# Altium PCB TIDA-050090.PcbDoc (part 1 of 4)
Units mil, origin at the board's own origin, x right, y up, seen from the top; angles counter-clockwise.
Board outline 4150 x 4140 mil, 8 copper layers (Top Layer 1, POWER1, GND1, SIGNAL1, SIGNAL2, GND2, POWER2, Bottom Layer 1), stack 60.703 mil thick; 130 components, 39 nets, 355 pads, 2292 vias.
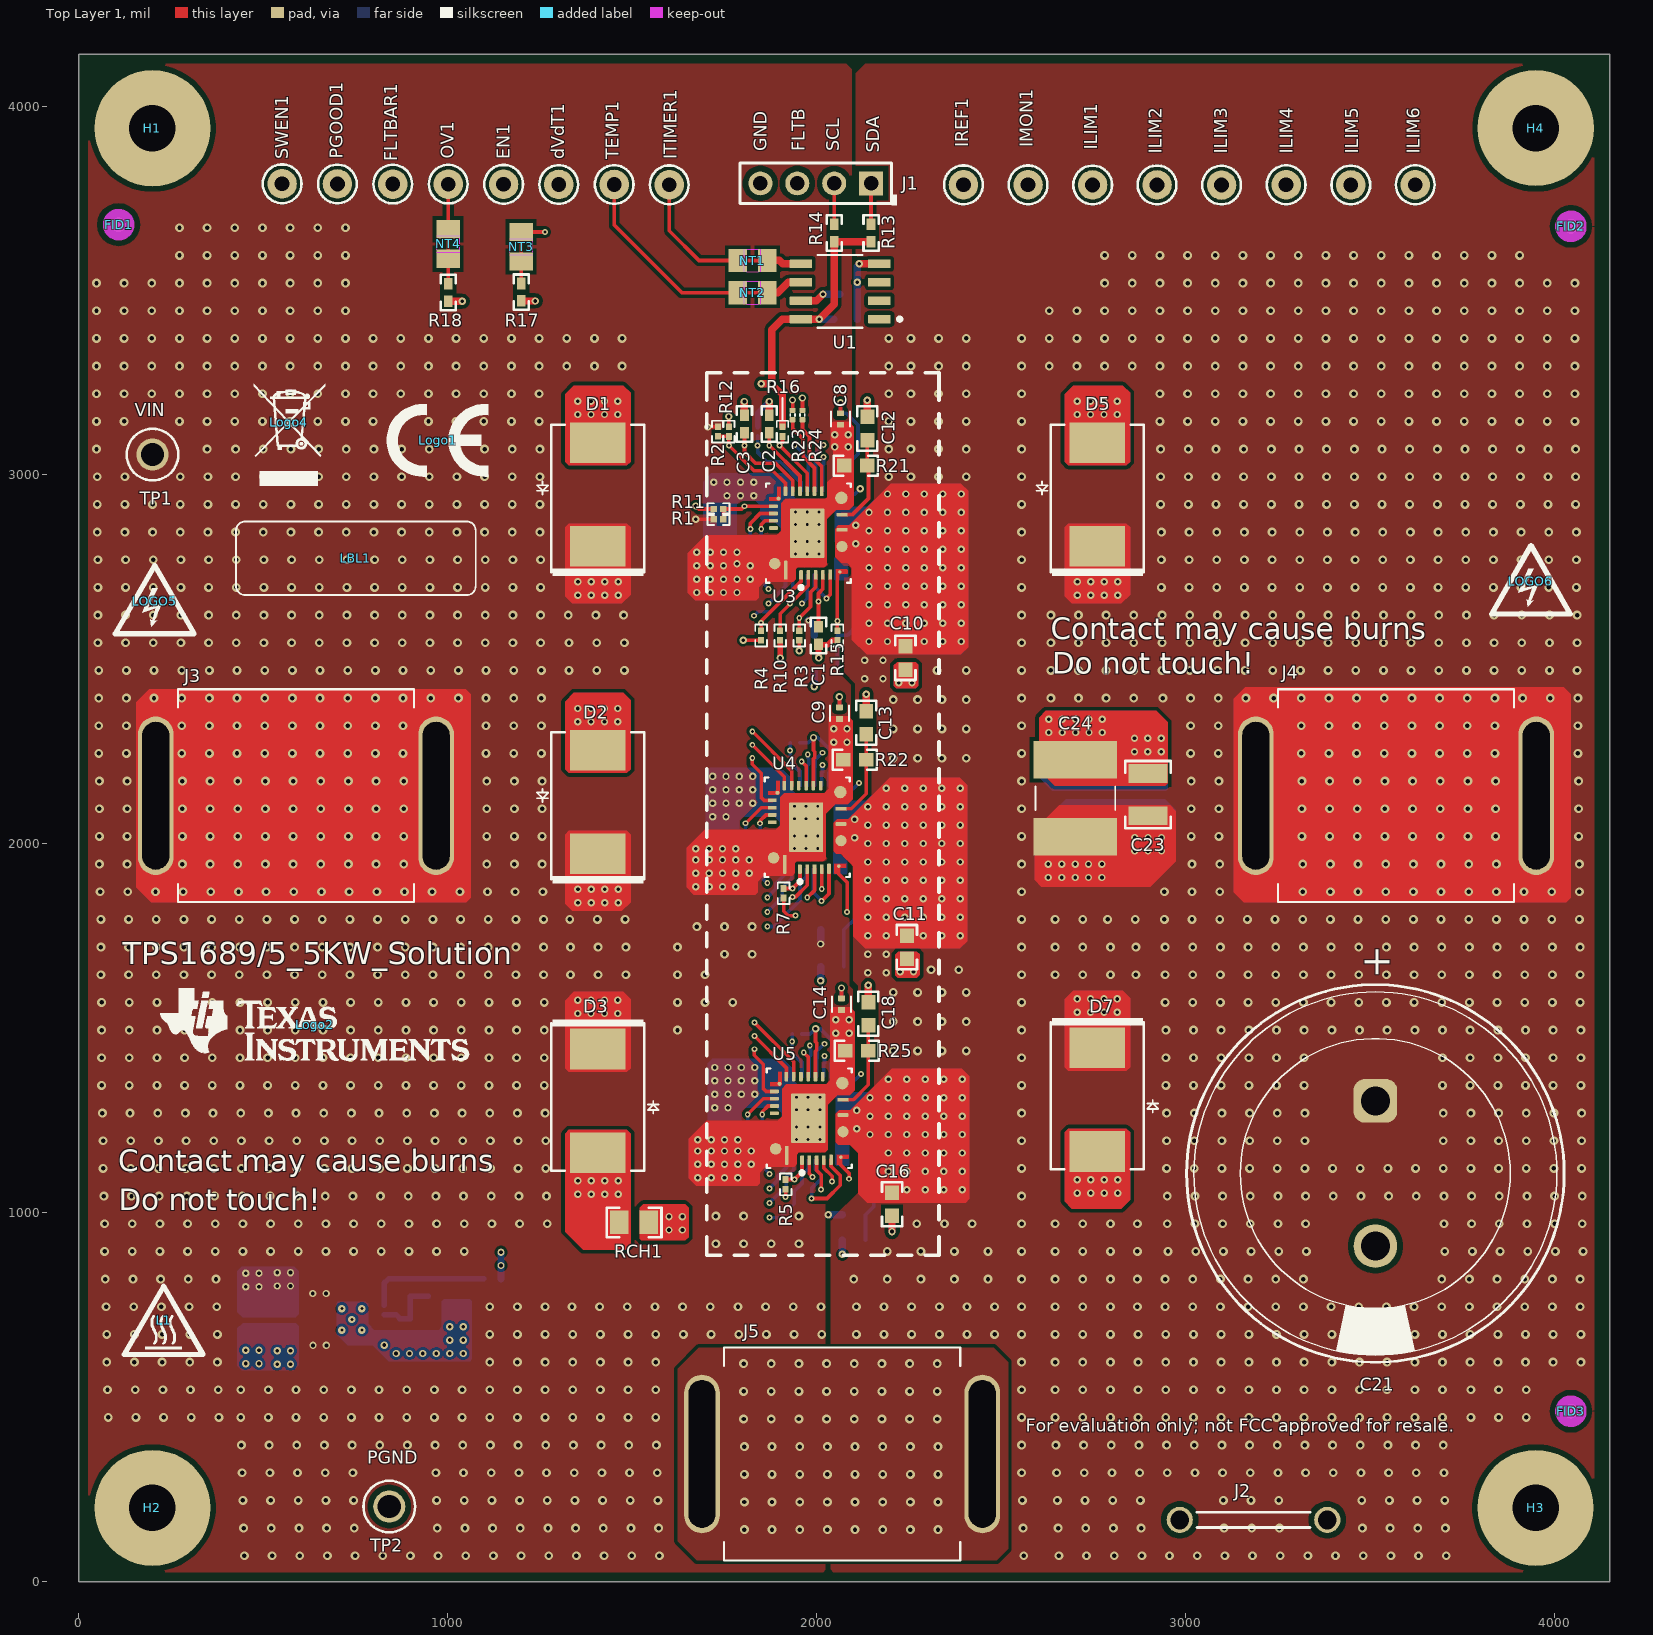
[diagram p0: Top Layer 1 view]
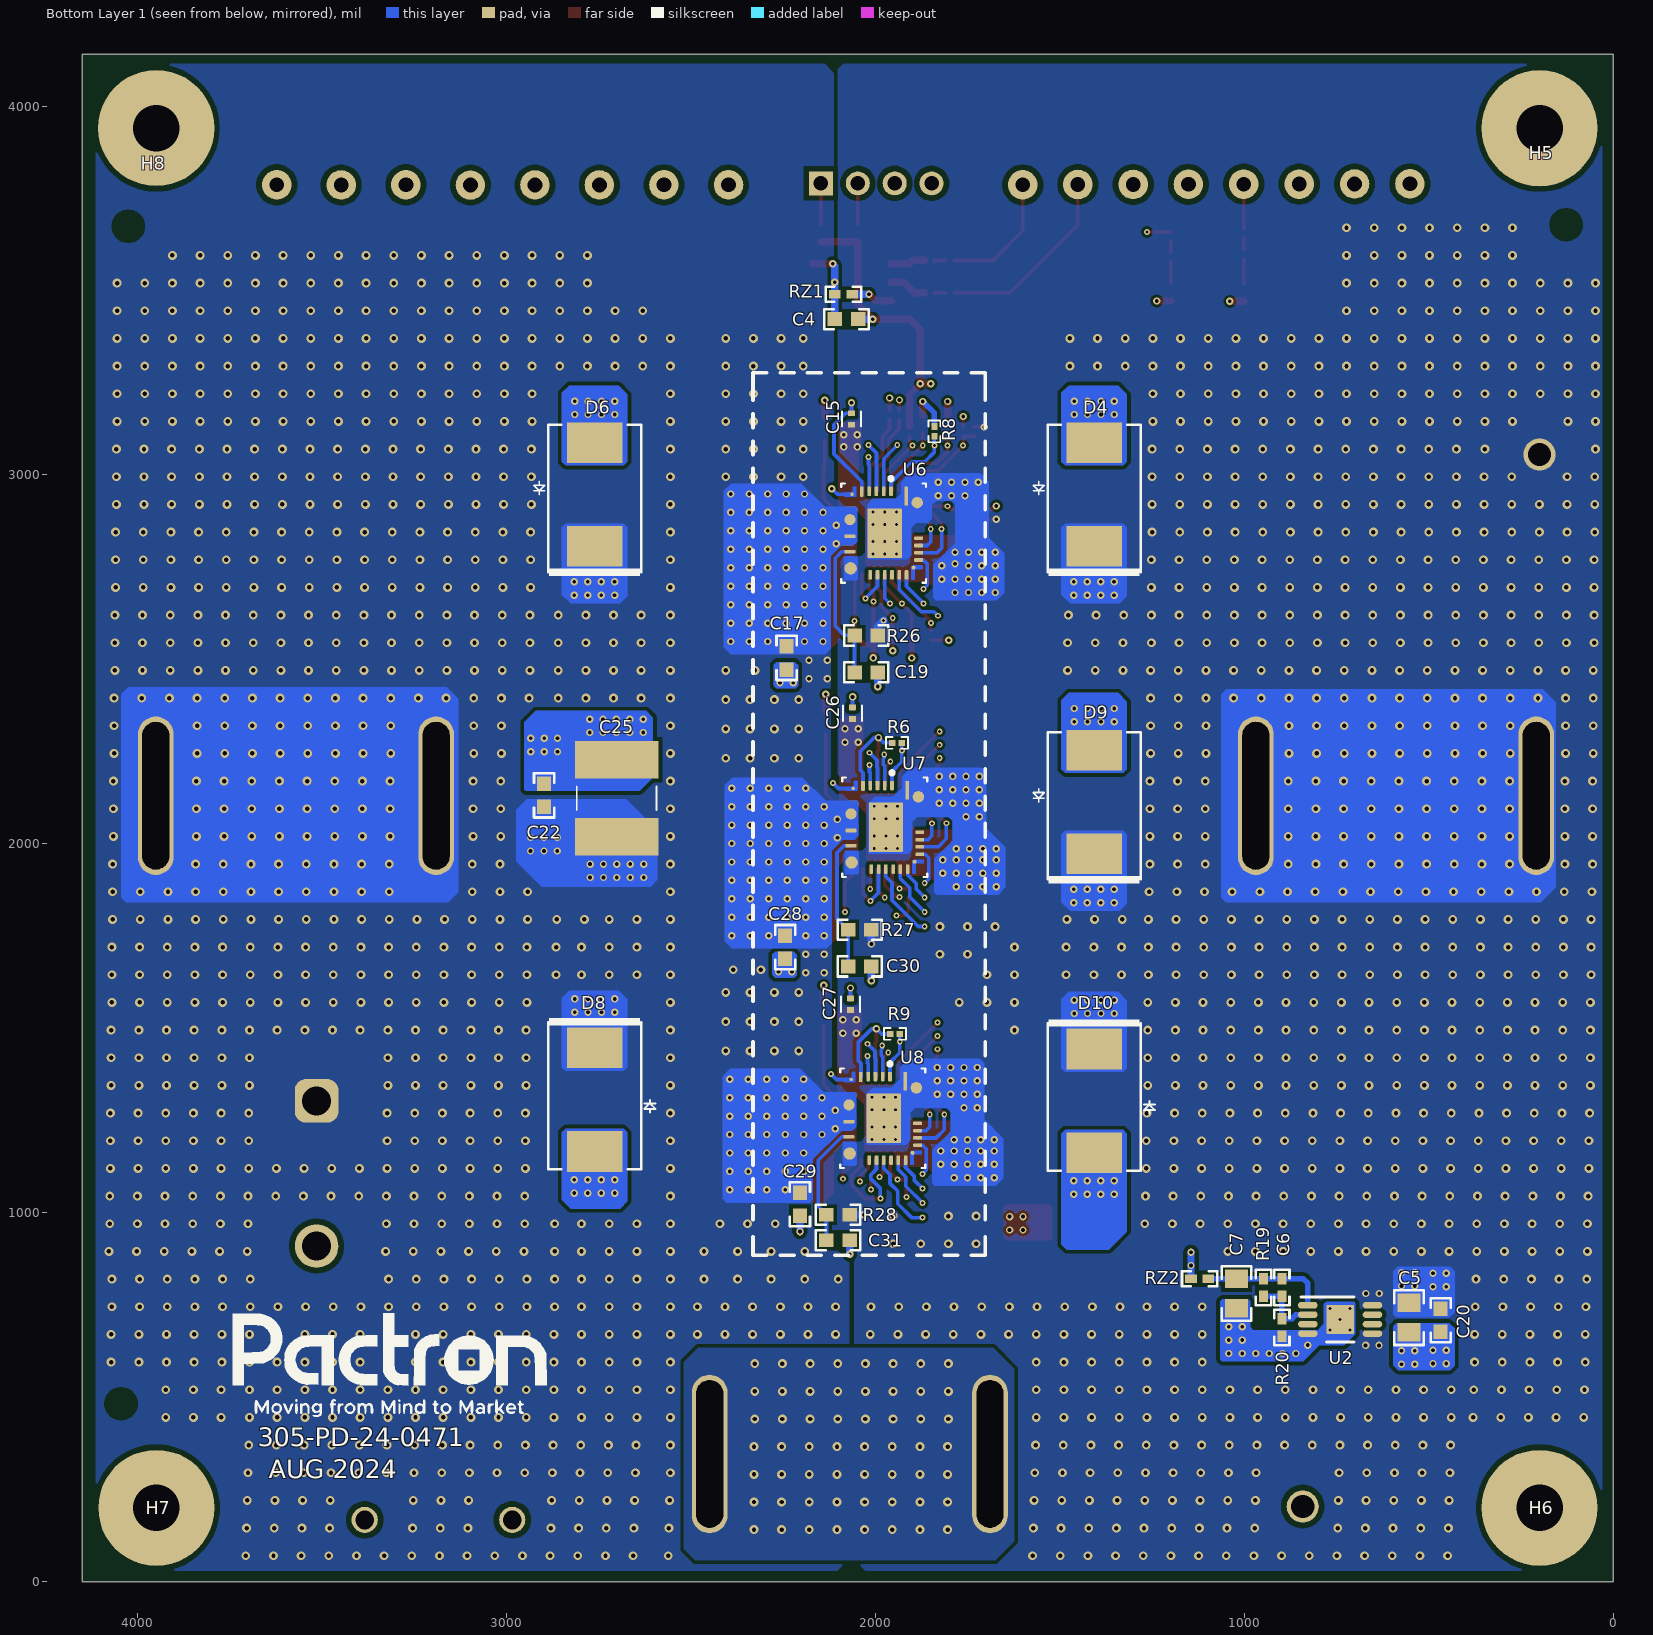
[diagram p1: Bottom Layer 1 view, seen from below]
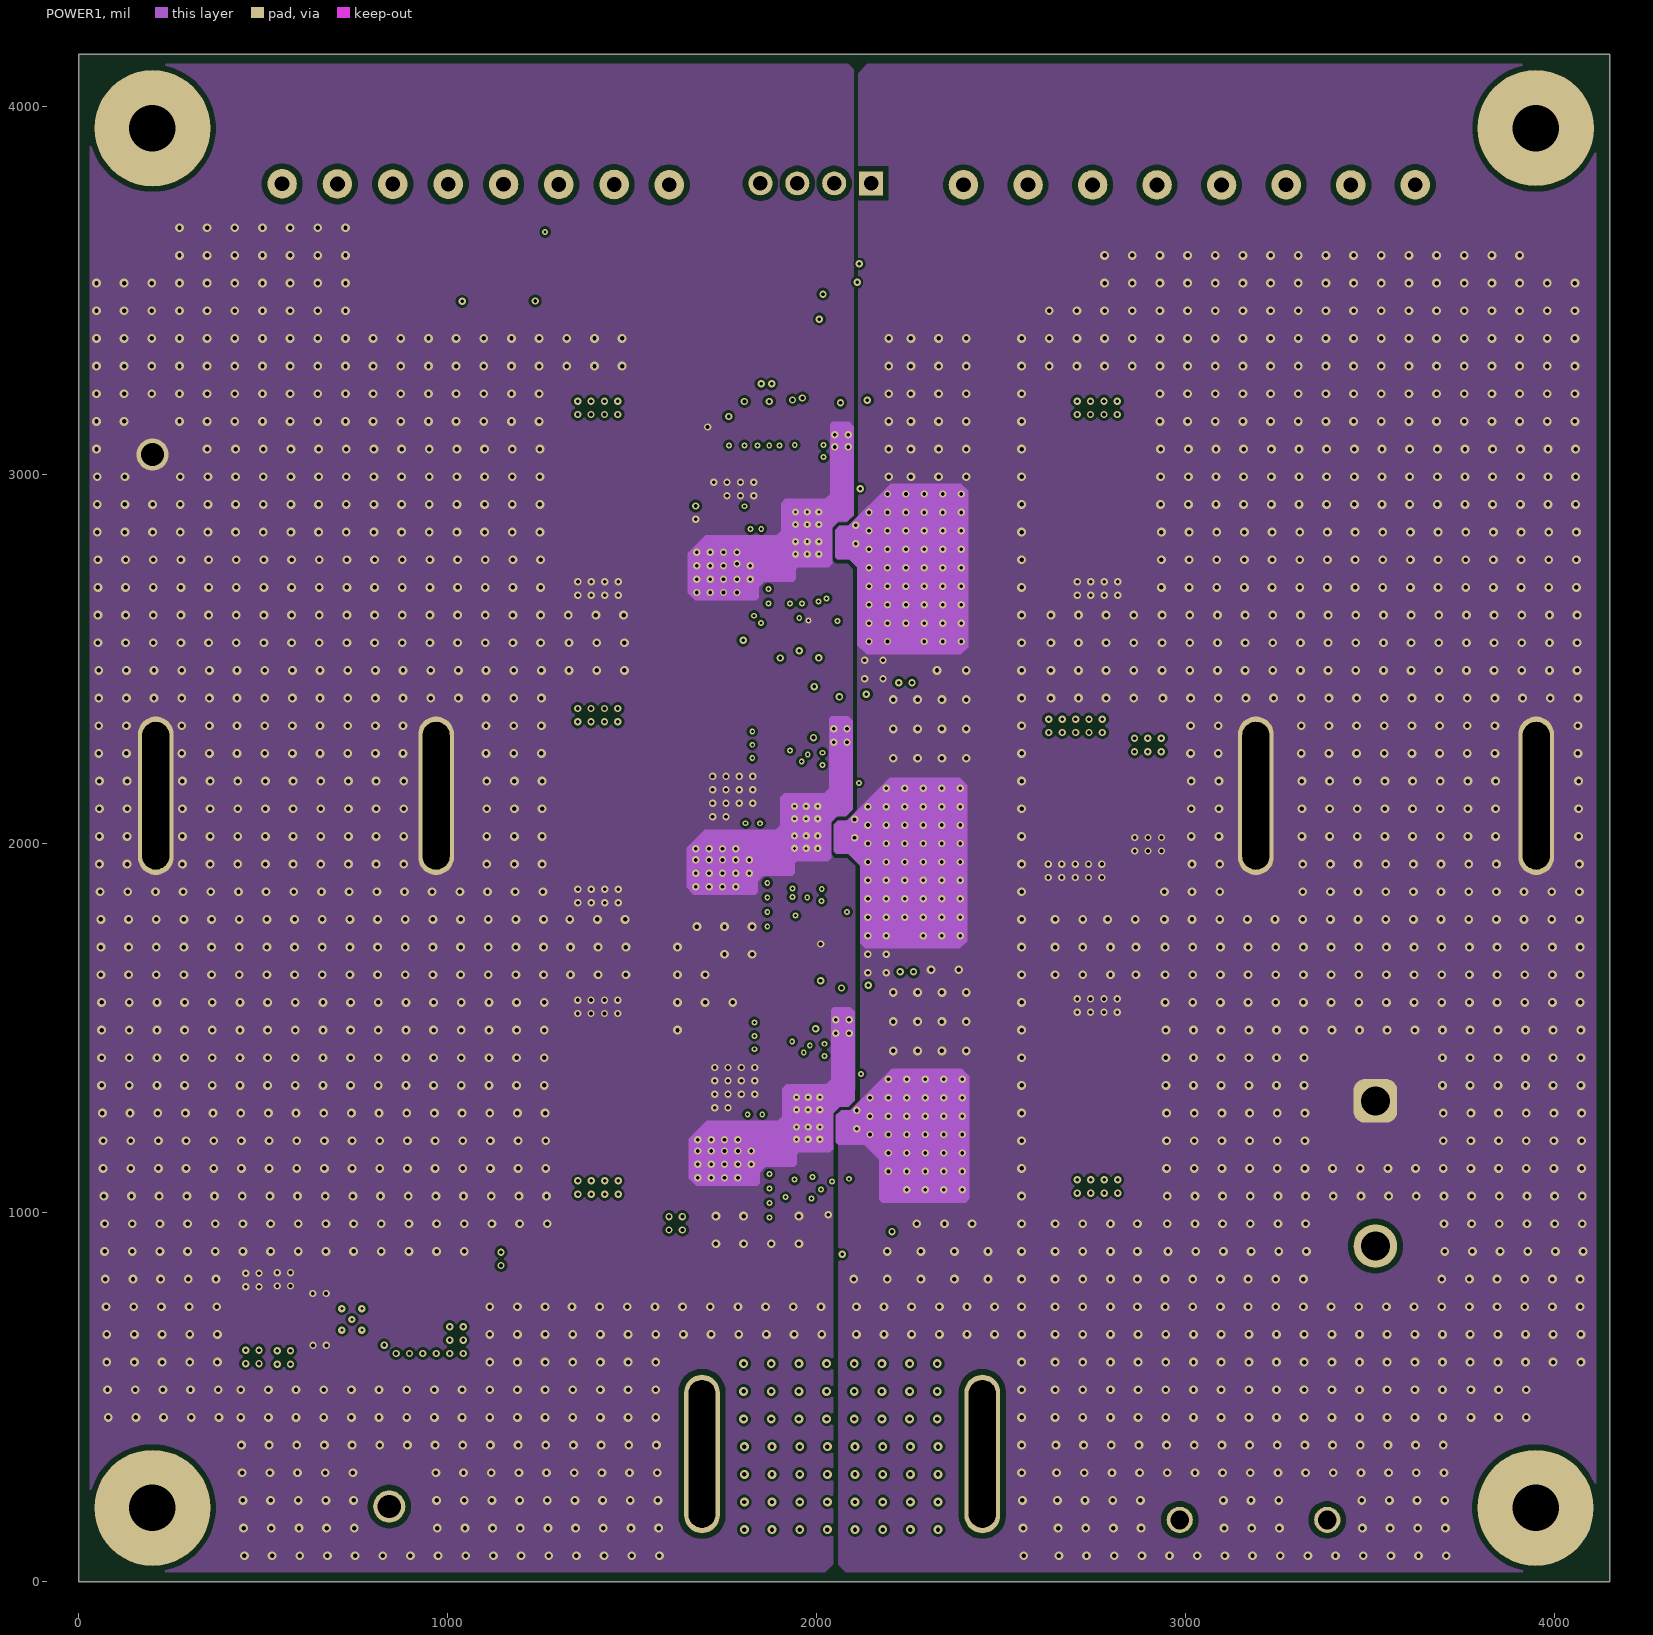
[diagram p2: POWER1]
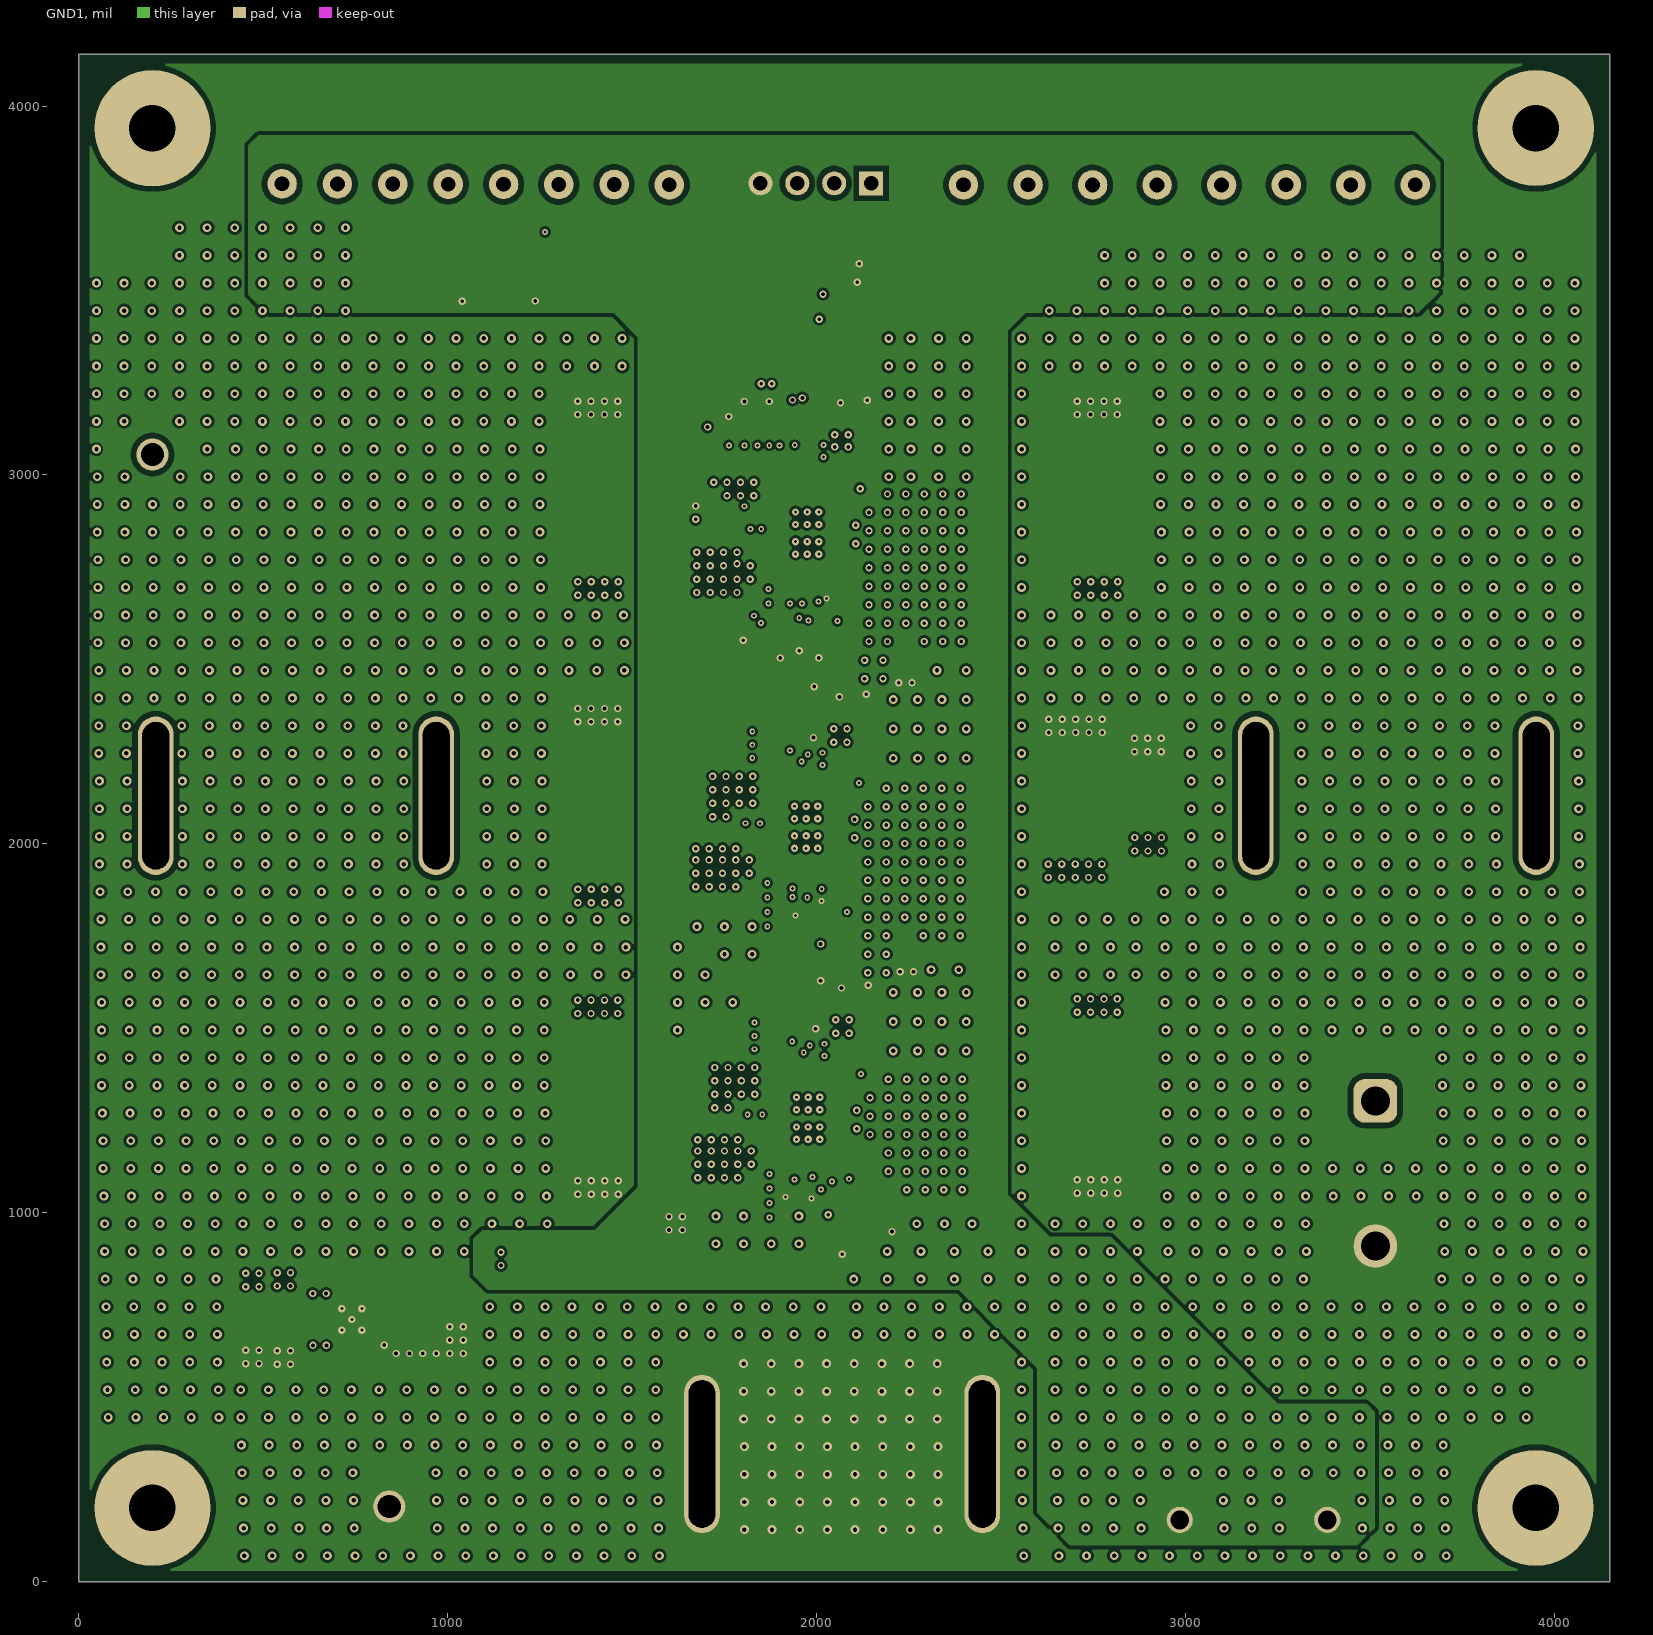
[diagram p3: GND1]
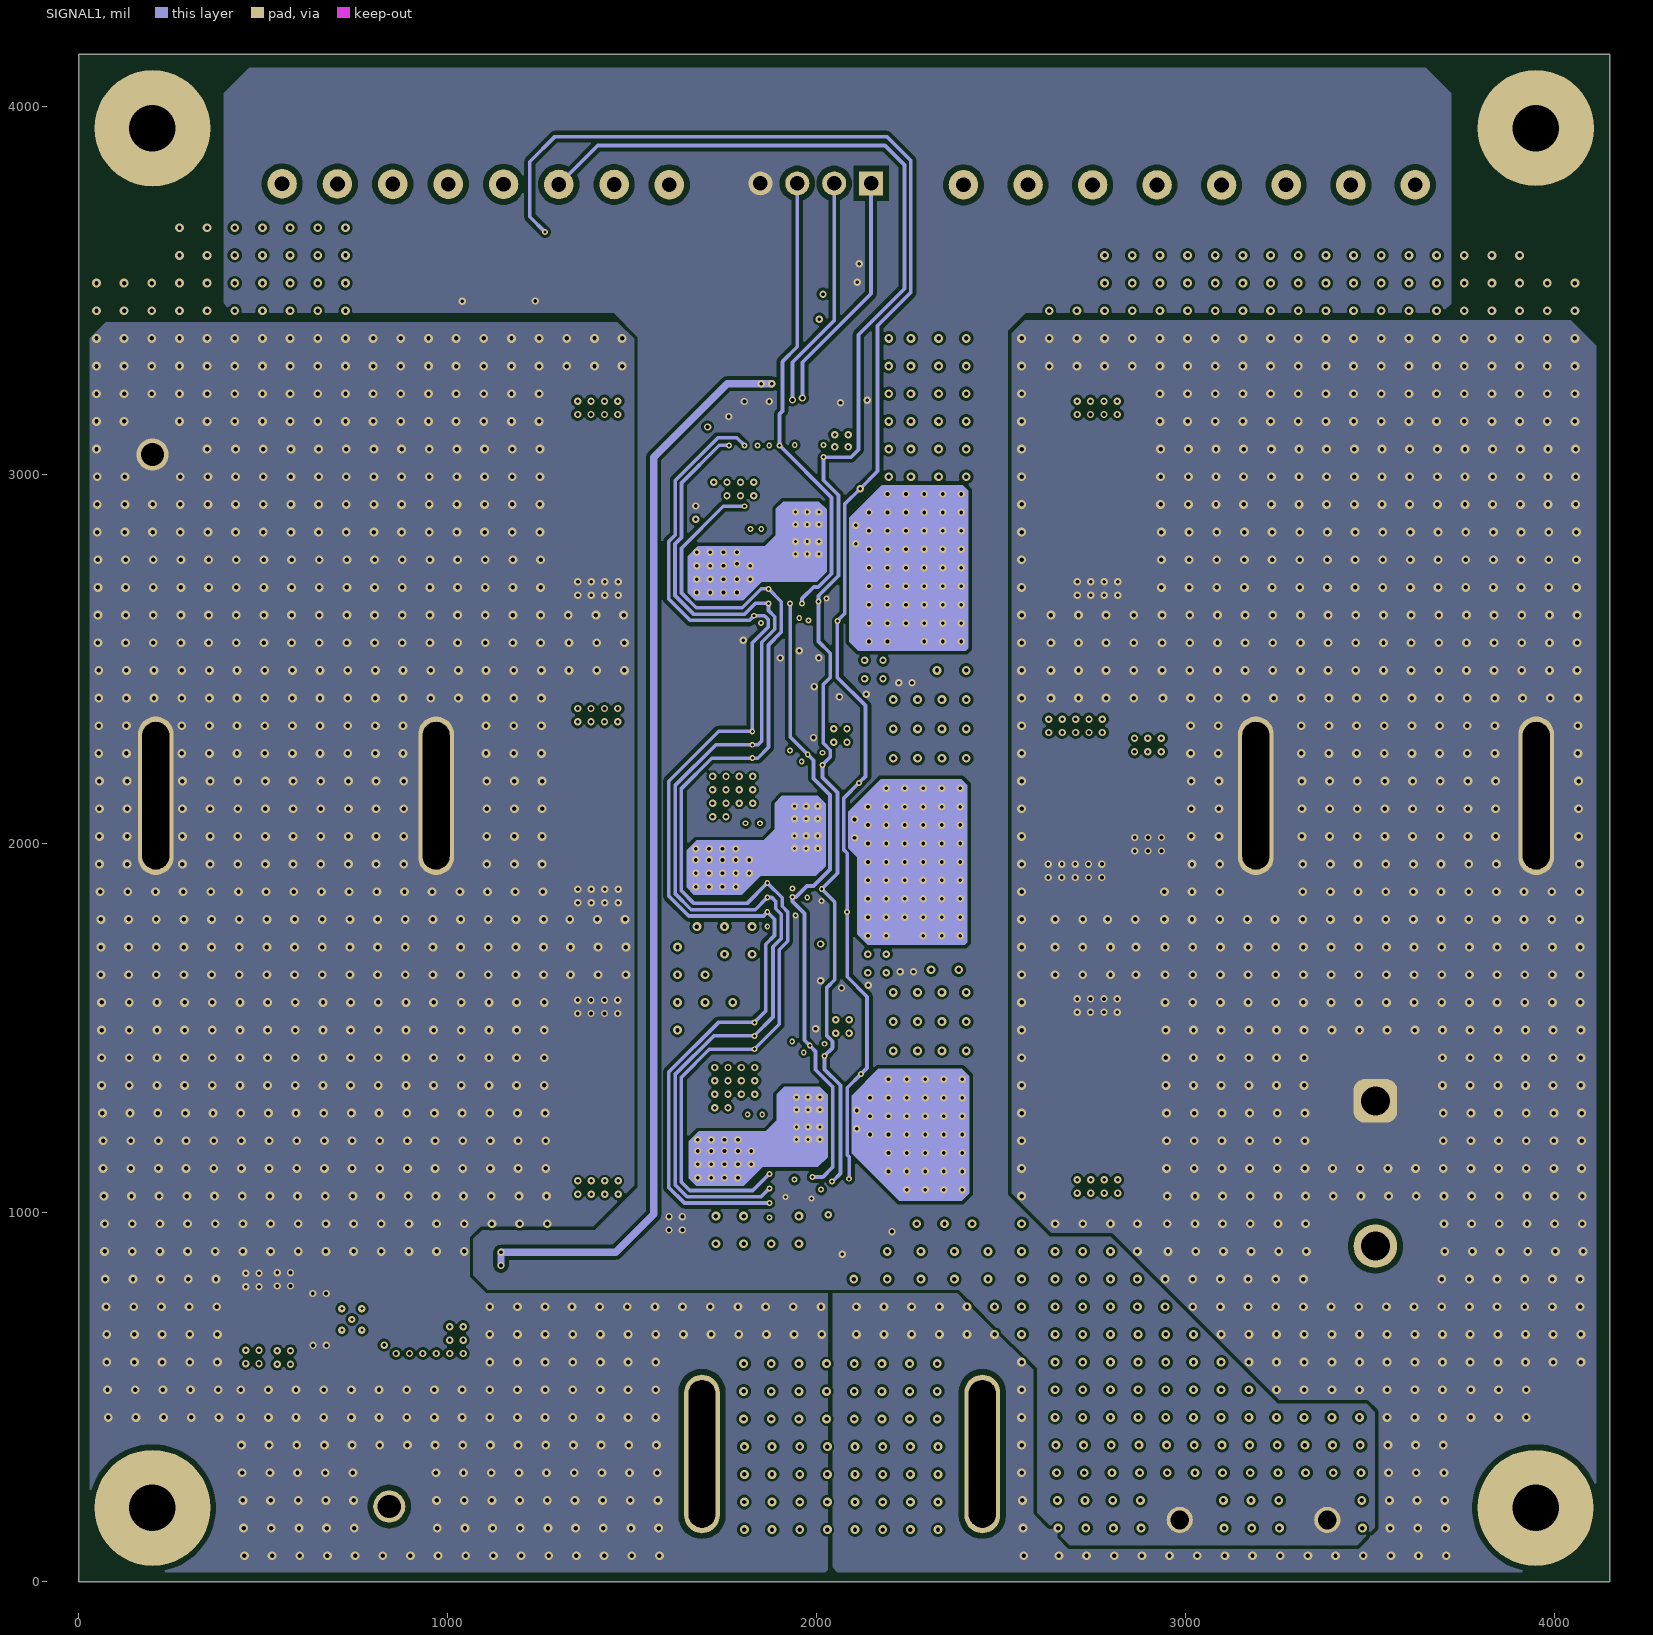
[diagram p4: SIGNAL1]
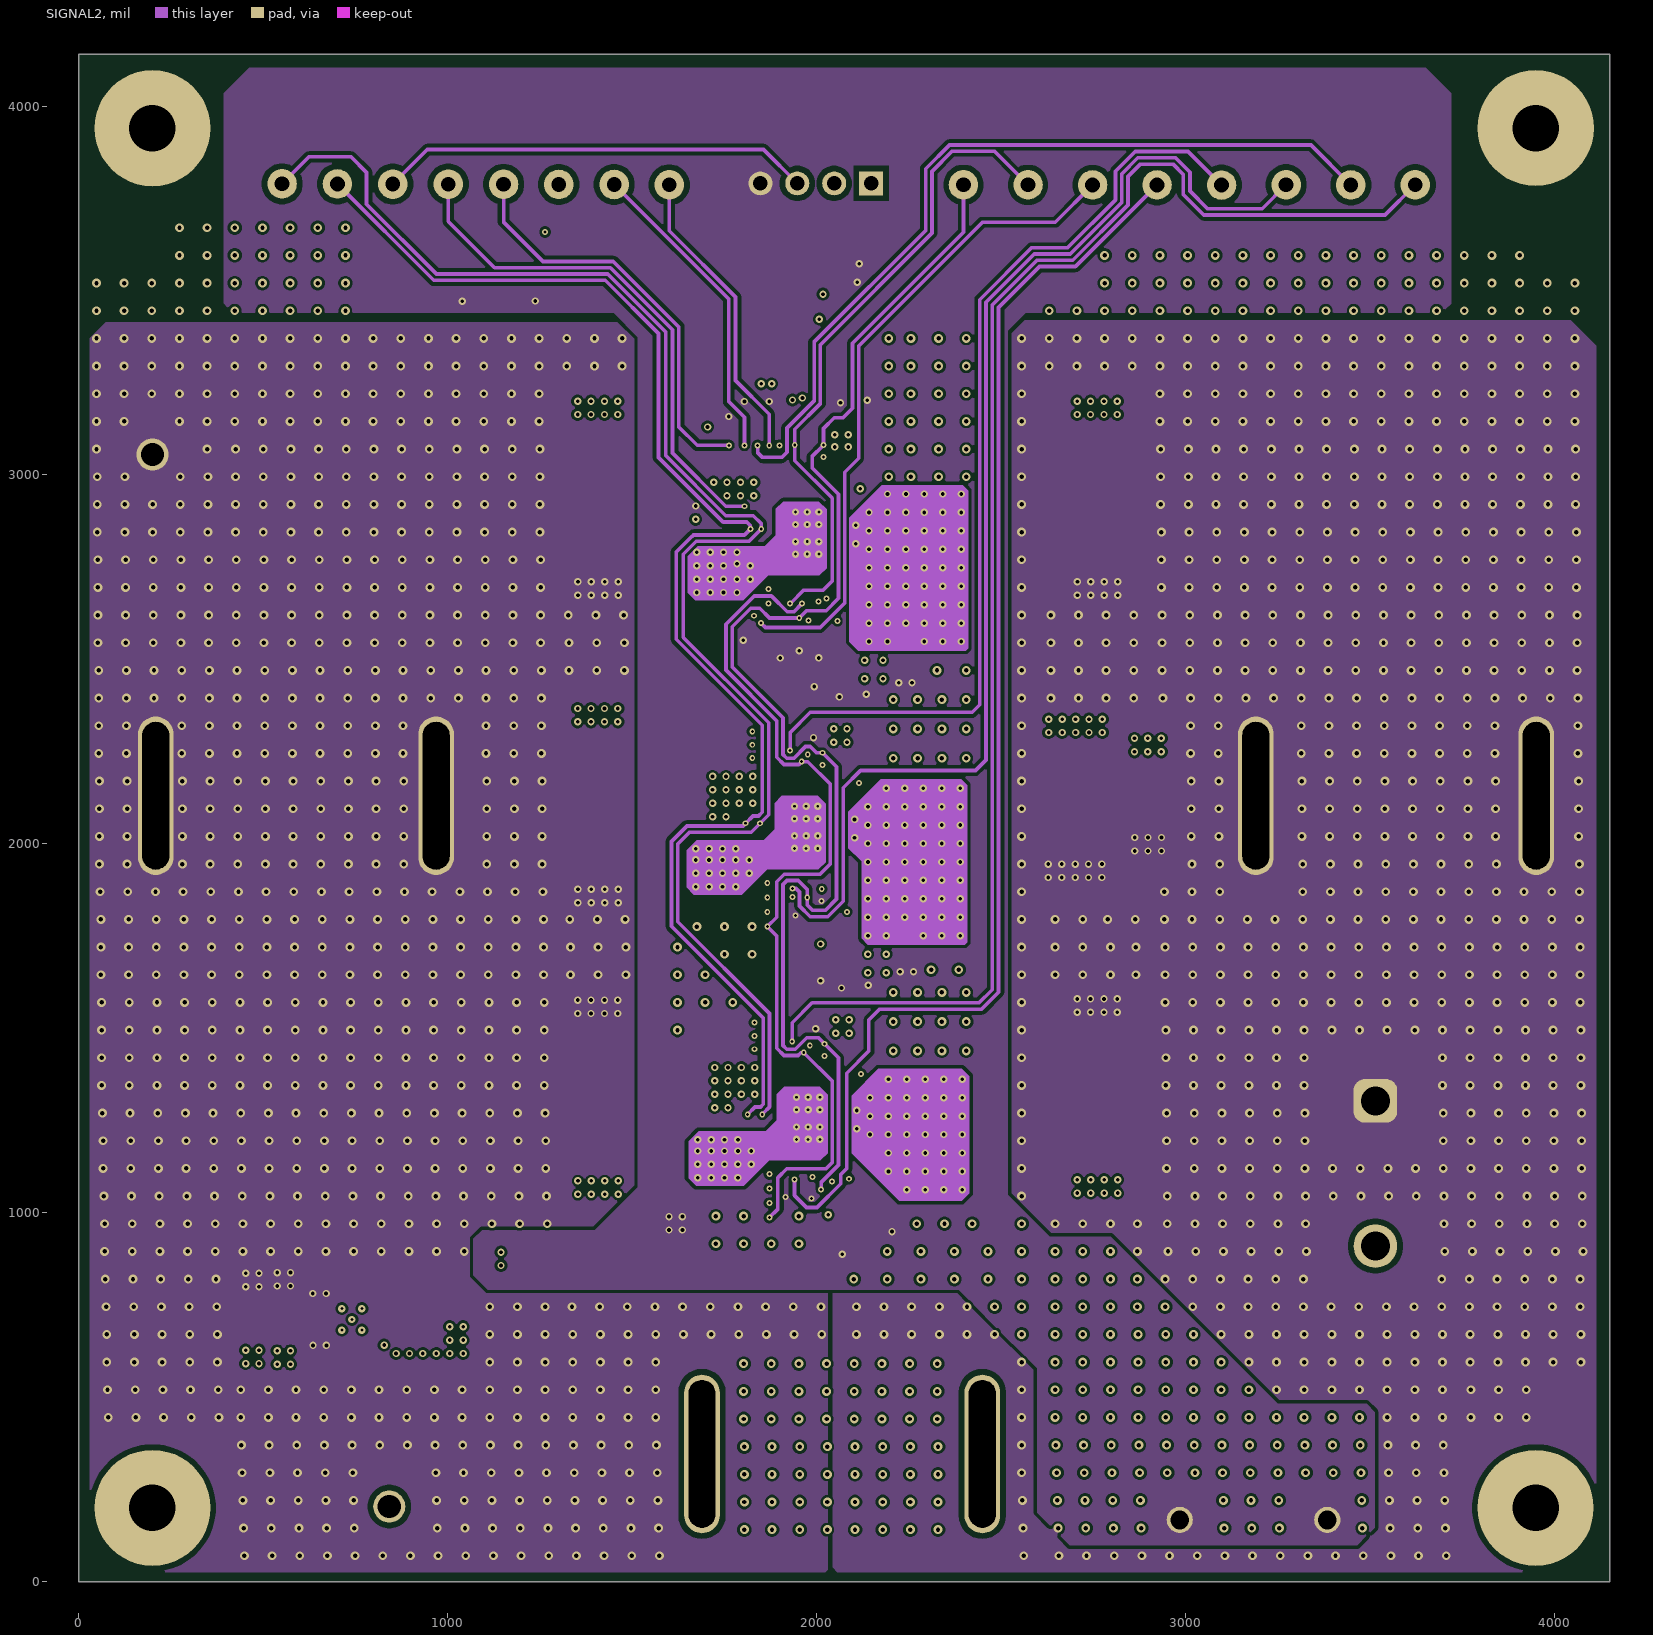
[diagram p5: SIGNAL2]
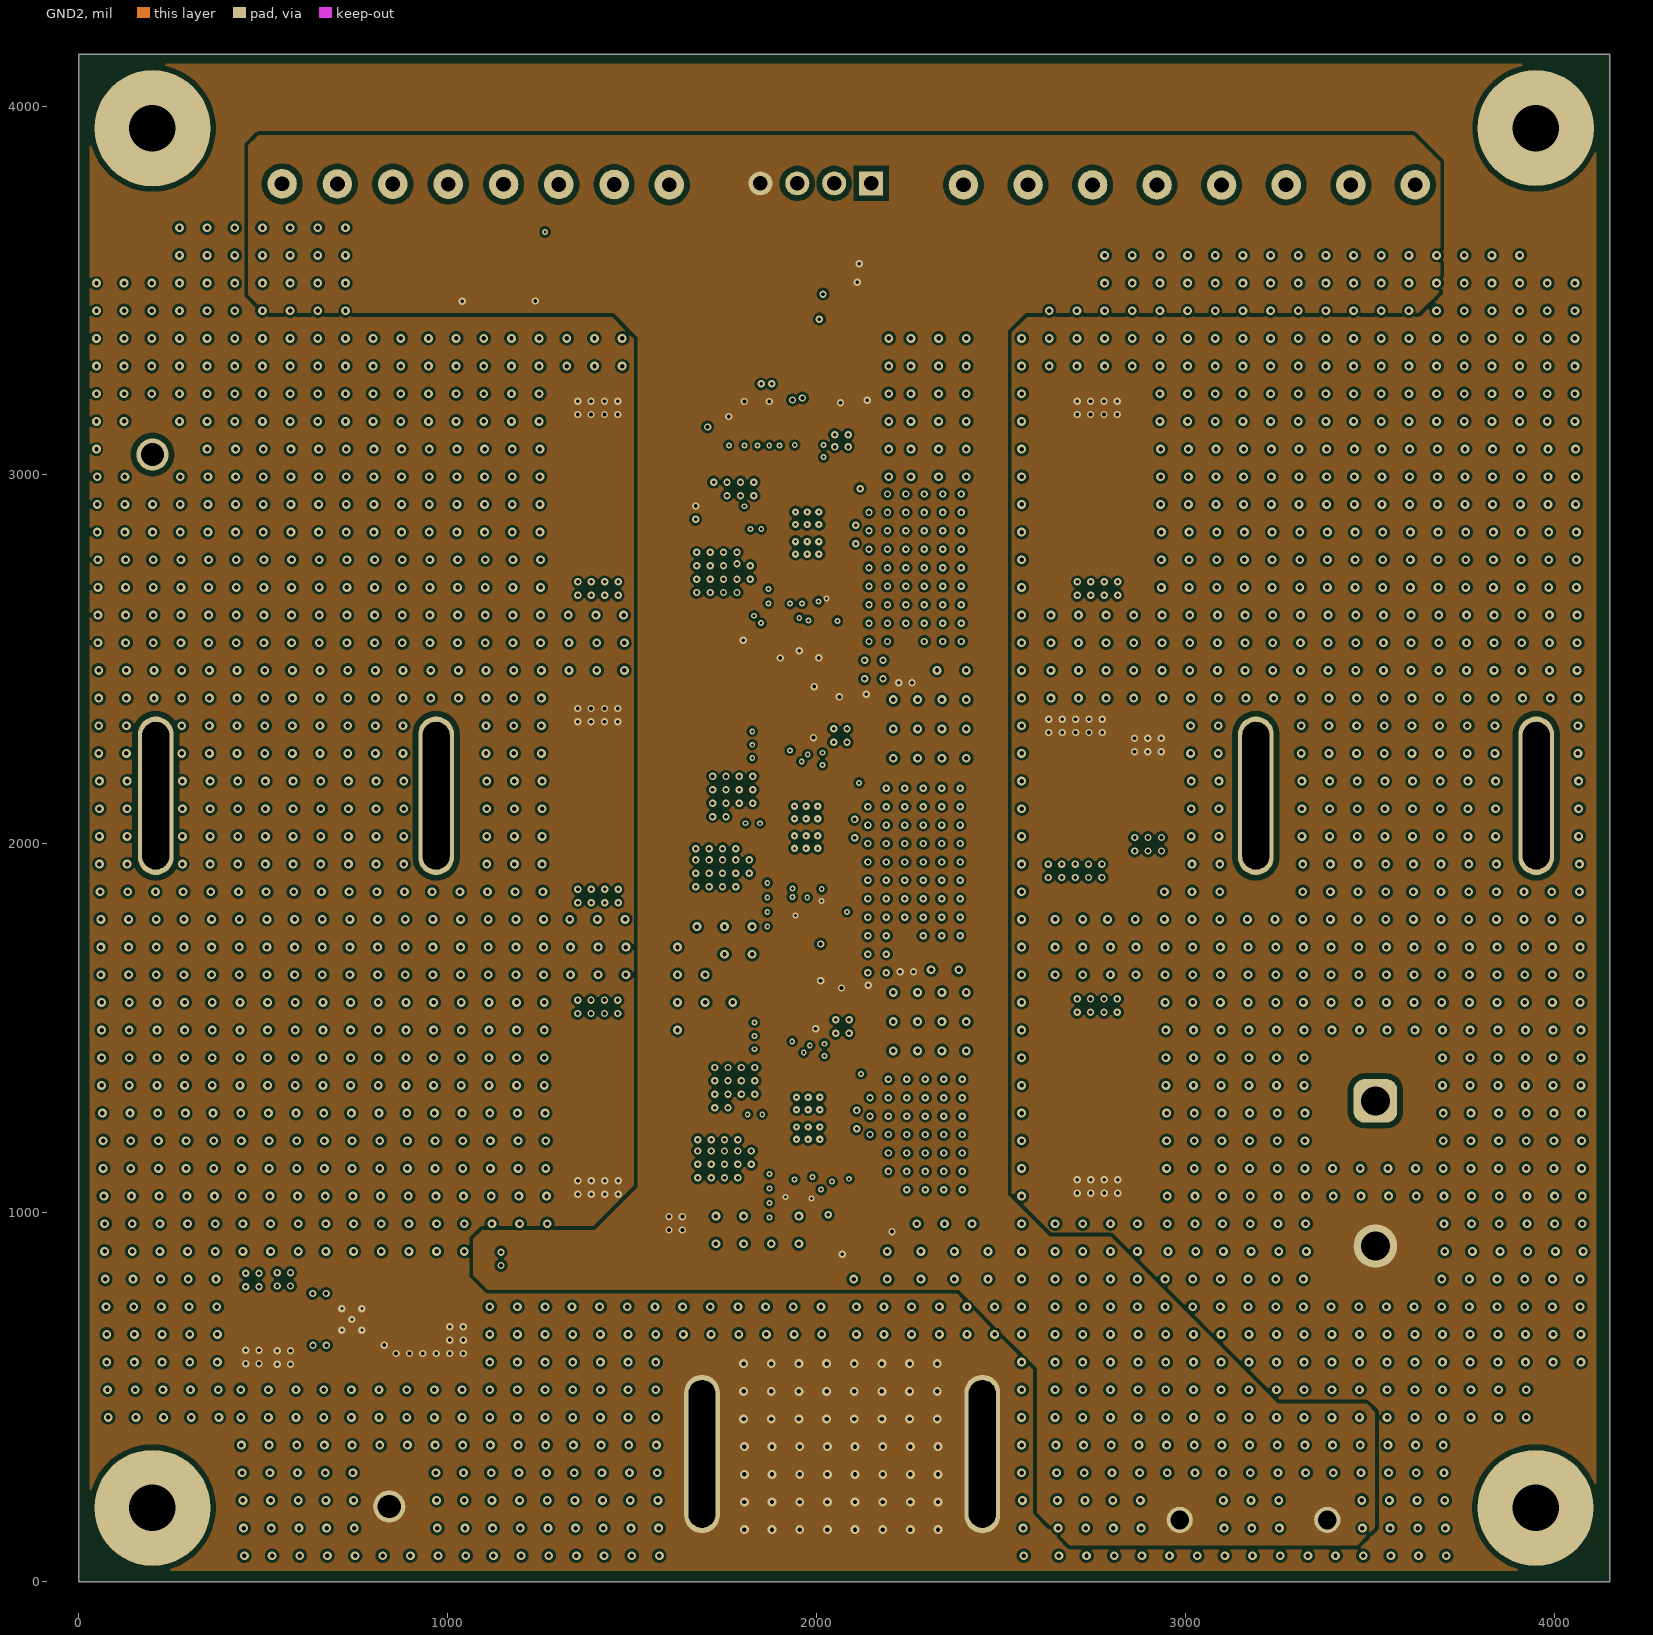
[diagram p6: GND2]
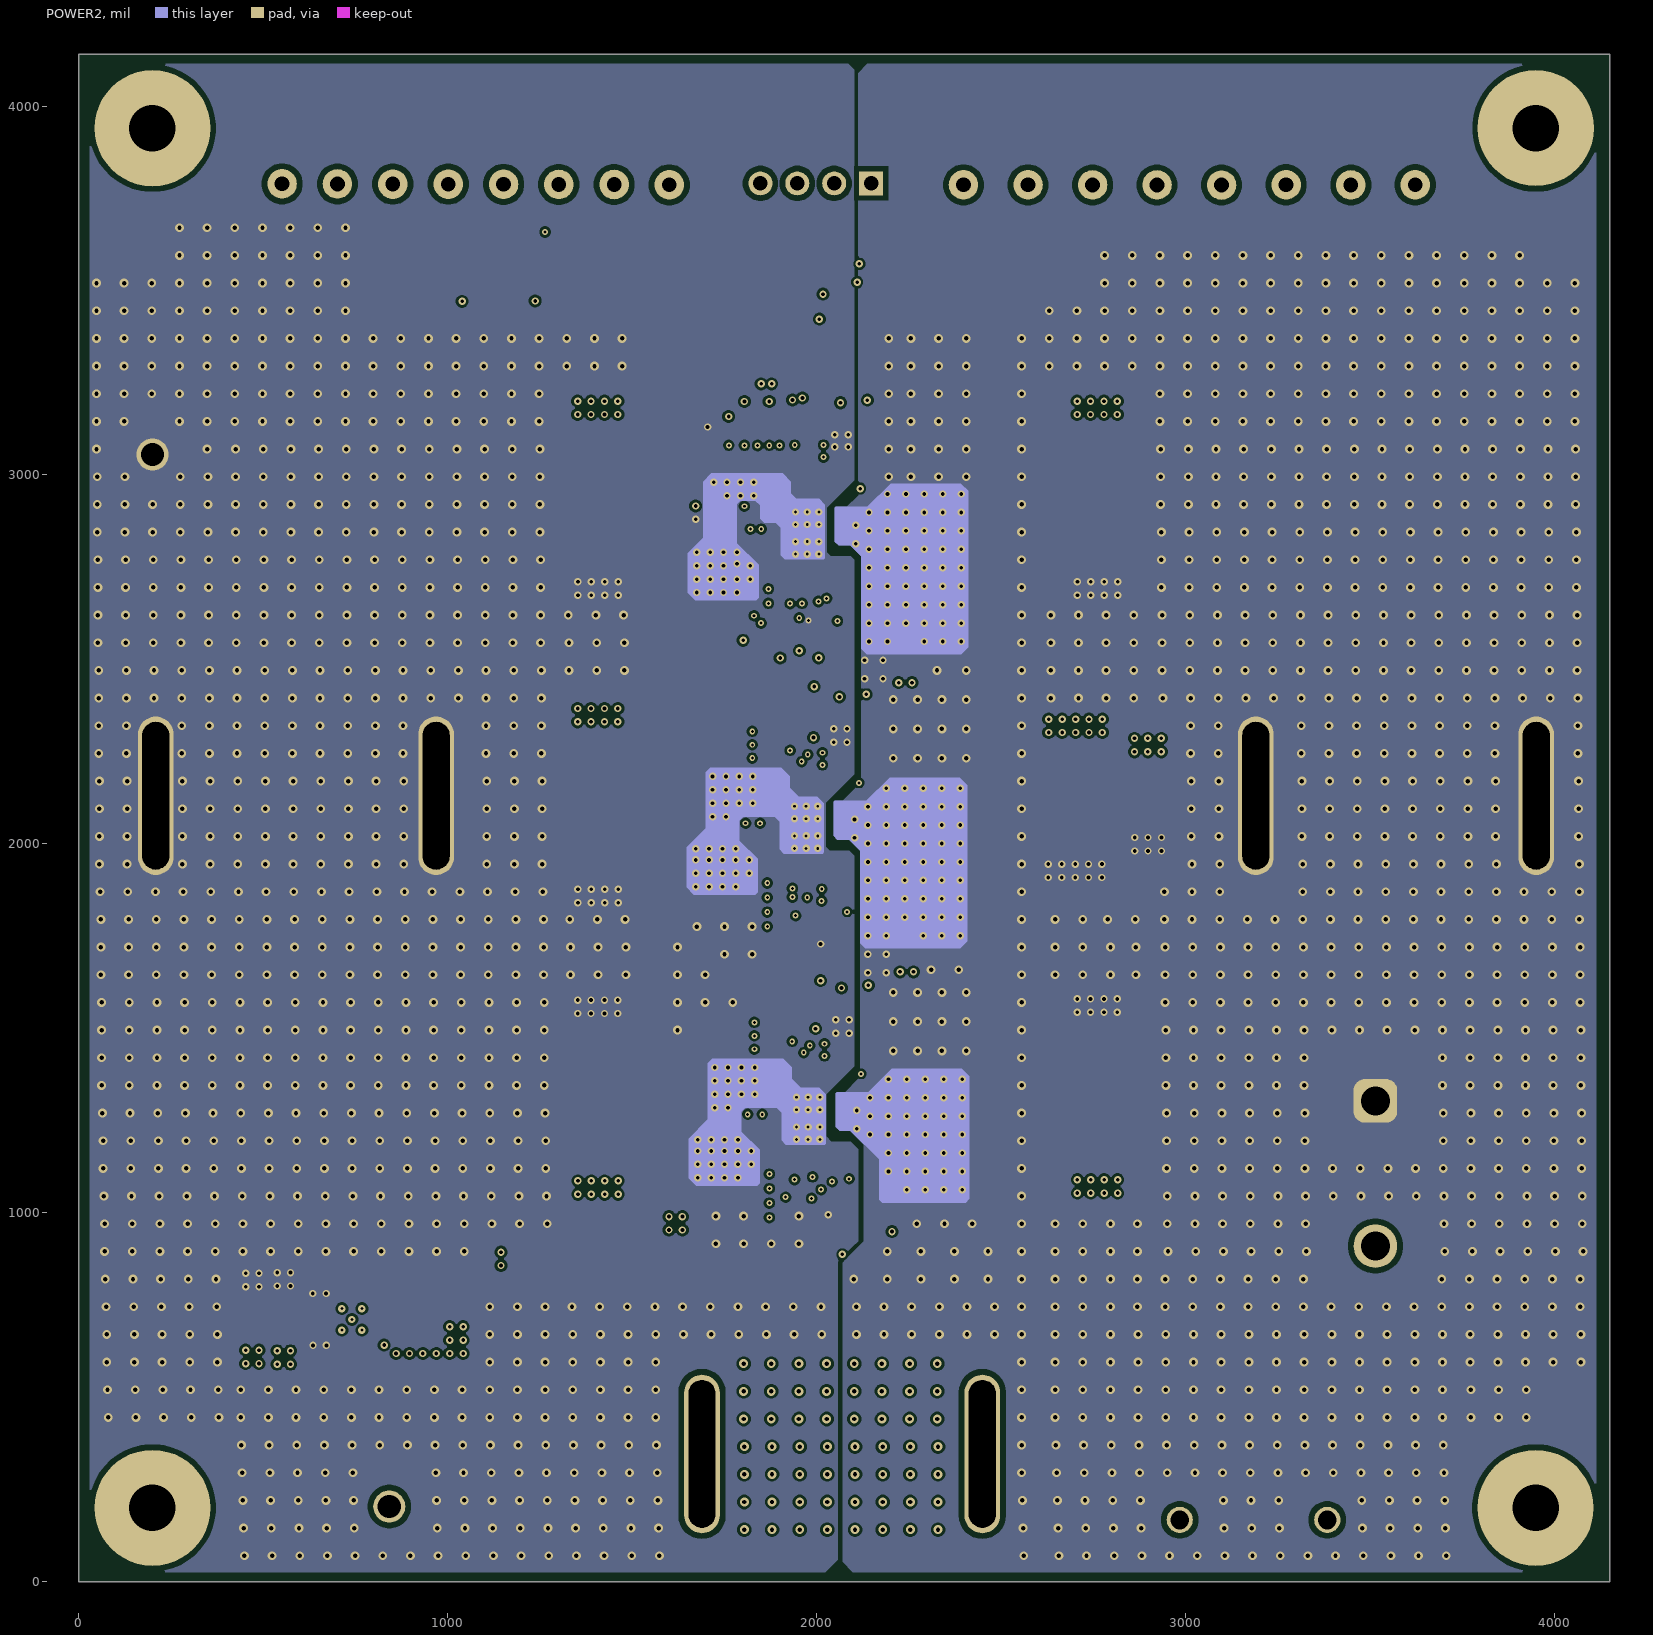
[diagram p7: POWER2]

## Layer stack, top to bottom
Top Solder: solder mask 1, Solder Resist, Dk 3.5
Top Layer 1: signal copper 2.756
Dielectric 1: prepreg 5.418, FR-4 High Tg, Dk 4.1
POWER1: signal copper 1.26
Dielectric 2: prepreg 8, FR-4 High Tg, Dk 4.1
GND1: signal copper 1.26
Dielectric 3: prepreg 6.396, FR-4 High Tg, Dk 4.1
SIGNAL1: signal copper 1.26
Dielectric 4: dielectric 8, FR-4 High Tg, Dk 4.8
SIGNAL2: signal copper 1.26
Dielectric 5: prepreg 6.396, FR-4 High Tg, Dk 4.1
GND2: signal copper 1.26
Dielectric 6: prepreg 8, FR-4 High Tg, Dk 4.1
POWER2: signal copper 1.26
Dielectric 7: prepreg 5.418, FR-4 High Tg, Dk 4.1
Bottom Layer 1: signal copper 2.759
Bottom Solder: solder mask 1, Solder Resist, Dk 3.5

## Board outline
0,0 4150,0 4150,4140 0,4140

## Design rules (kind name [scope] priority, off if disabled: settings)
AcuteAngle [All] p1: minimum=4.50000000000000E+0001 checktracksonly=FALSE
AssemblyTestPointUsage [All] p1: valid=2
BoardOutlineClearance BoardOutlineClearance_MountingHoles [OnCopper and InComponentClass('Mounting Holes')] p1: gap=39.37 ignorepadtopadclearanceinfootprint=FALSE
BoardOutlineClearance BoardOutlineClearance_Poly [OnCopper and IsPoly] p2: gap=25 ignorepadtopadclearanceinfootprint=FALSE
BoardOutlineClearance [OnCopper and Not InComponentClass('Logo') and not InComponentClass('FiducialMark') and not InRegion(1000,500,4000,800) and not InPoly] p3: gap=20 ignorepadtopadclearanceinfootprint=FALSE
Clearance [All] p1: gap=7 ignorepadtopadclearanceinfootprint=TRUE except(6: Track-Via; 10: Track-Poly SMDPad-Poly Poly-Poly Poly-Region; 15: Arc-Poly Arc-Region THPad-Poly Fill-Poly Fill-Region)
Clearance Clearance_Keepouts [((IsTrack Or IsArc) And Not InPoly) And IsFree and IsKeepOut vs ((IsTrack Or IsArc) And Not InPoly) And IsFree and IsKeepOut] p2: gap=0 ignorepadtopadclearanceinfootprint=FALSE
Clearance Clearance_Poly [InPolygon] p3: gap=10 ignorepadtopadclearanceinfootprint=TRUE
Clearance Clearance_FiducialMark [IsKeepOut and InComponentClass('FiducialMark') vs IsPad and InComponentClass('FiducialMark')] p4: gap=0 ignorepadtopadclearanceinfootprint=FALSE
ComponentClearance ComponentClearance_MountingHoles_FiducialMarks [InComponentClass('Mounting Holes') vs InComponentClass('FiducialMark')] p1: gap=50 collisioncheckmode=3 verticalgap=10 showdistances=FALSE
ComponentClearance ComponentClearance_Shunt [InComponentClass('Header') vs InComponentClass('Shunt')] p2: gap=0 collisioncheckmode=3 verticalgap=0 showdistances=FALSE
ComponentClearance ComponentClearance_Logo [InComponentClass('Logo')] p3: gap=30 collisioncheckmode=3 verticalgap=10 showdistances=FALSE
ComponentClearance ComponentClearance_ScrewToNut [(HasFootprint('NY PMS 440 0025 PH')) vs (HasFootprint('Keystone_1902C'))] p4: gap=5 collisioncheckmode=3 verticalgap=10 showdistances=FALSE
ComponentClearance ComponentClearance_MountingHoles [InComponentClass('Mounting Holes')] p5: gap=100 collisioncheckmode=3 verticalgap=100000 showdistances=FALSE
ComponentClearance ComponentClearance_SmallPassives [HasFootprint('0201*') or HasFootprint('0402*') or HasFootprint('0508') or HasFootprint('0603*') or HasFootprint('0612') or HasFootprint('0805*') or HasFootprint('0815*') or HasFootprint('0830*') or HasFootprint('1206*') or HasFootprint('1210*') or HasFootprint('1808*') or HasFootprint('1812*') or HasFootprint('1825*') or HasFootprint('2010*') or HasFootprint('2220*') or HasFootprint('2225*') or HasFootprint('2512*') or HasFootprint('2728*') or HasFootprint('3518*') vs HasFootprint('0201*') or HasFootprint('0402*') or HasFootprint('0508') or HasFootprint('0603*') or HasFootprint('0612') or HasFootprint('0805*') or HasFootprint('0815*') or HasFootprint('0830*') or HasFootprint('1206*') or HasFootprint('1210*') or HasFootprint('1808*') or HasFootprint('1812*') or HasFootprint('1825*') or HasFootprint('2010*') or HasFootprint('2220*') or HasFootprint('2225*') or HasFootprint('2512*') or HasFootprint('2728*') or HasFootprint('3518*')] p6: gap=14.96 collisioncheckmode=3 verticalgap=10 showdistances=FALSE
ComponentClearance ComponentClearance_THtoSMT [IsThruComponent vs IsSMTComponent] p7: gap=30 collisioncheckmode=3 verticalgap=30 showdistances=FALSE
ComponentClearance ComponentClearance_THtoTH [IsThruComponent vs IsThruComponent] p8: gap=20 collisioncheckmode=3 verticalgap=30 showdistances=FALSE
ComponentClearance [All] p9: gap=20 collisioncheckmode=3 verticalgap=10 showdistances=FALSE
DiffPairsRouting [All] p1: maxlimit=100 minlimit=10 mostfreqgap=10 toplayer_minwidth=15 toplayer_maxwidth=15 toplayer_prefwidth=15 midlayer1_minwidth=15 midlayer1_maxwidth=15 midlayer1_prefwidth=15 midlayer2_minwidth=15 midlayer2_maxwidth=15 midlayer2_prefwidth=15 midlayer4_minwidth=15 midlayer4_maxwidth=15 midlayer4_prefwidth=15 midlayer7_minwidth=15 midlayer7_maxwidth=15 midlayer7_prefwidth=15 midlayer9_minwidth=15 midlayer9_maxwidth=15 midlayer9_prefwidth=15 midlayer10_minwidth=15 midlayer10_maxwidth=15 midlayer10_prefwidth=15 bottomlayer_minwidth=15 bottomlayer_maxwidth=15 bottomlayer_prefwidth=15 maxuncoupledlength=1000
FabricationTestPointUsage TestPointUsage [All] p1: valid=2 allowmultiple=FALSE
FabricationTestpoint Testpoint [All] p1: side=3 testpointundercomponent=TRUE minsize=40 maxsize=100 preferedsize=60 minholesize=0 maxholesize=40 preferedholesize=32 testpointgrid=1 allowsidetop=TRUE allowsidebottom=TRUE usegrid=TRUE gridtolerance=0.01
FanoutControl Fanout_LCC [IsLCC] p1: bgadir=Out bgaviamode=Centered fanoutstyle=Auto fanoutdirection=Alternating viagrid=1 // Fanout_LCC (Default Rule)
FanoutControl Fanout_BGA [IsBGA] p2: bgadir=Out bgaviamode=Centered fanoutstyle=Auto fanoutdirection=Alternating viagrid=1 // Fanout_BGA (Default Rule)
FanoutControl Fanout_Default [All] p4: bgadir=Out bgaviamode=Centered fanoutstyle=Auto fanoutdirection=Alternating viagrid=1 // Fanout_Default (Default Rule)
FanoutControl Fanout_Small [(CompPinCount < 5)] p5: bgadir=Out bgaviamode=Centered fanoutstyle=Auto fanoutdirection=OutThenIn viagrid=1 // Fanout_Small (Default Rule)
HoleSize [All] p1: absolutevalues=TRUE maxlimit=251 minlimit=7.87 maxpercent=80.000 minpercent=20.000
MinimumAnnularRing MinimumAnnularRing_ThermalPadVias [IsVia and InAnyComponent] p1: minimumring=5.91
MinimumAnnularRing [All] p2: minimumring=7.87
MinimumSolderMaskSliver MinimumSolderMaskSliver_Logo [InComponentClass('Logo') vs InComponentClass('Logo')] p1: minsoldermaskwidth=0.7
MinimumSolderMaskSliver [All] p2: minsoldermaskwidth=3.94
PlaneConnect [All] p1: planeconnectstyle=Direct reliefexpansion=10 reliefentries=4 reliefconductorwidth=10 reliefairgap=10
PolygonConnect [All] p1: connectstyle=Direct reliefconductorwidth=10 reliefentries=4 polygonreliefangle="90 Angle" airgapwidth=10
RoutingLayers [All] p1: top layer_v5=TRUE mid layer 1_v5=FALSE mid layer 2_v5=FALSE mid layer 4_v5=FALSE mid layer 7_v5=FALSE mid layer 9_v5=FALSE mid layer 10_v5=FALSE bottom layer_v5=TRUE
RoutingVias ThermalPadVias [IsVia and InAnyComponent] p1: holewidth=7.87 width=19.68 viastyle="Through Hole" minholewidth=7.87 minwidth=19.68 maxholewidth=12.99 maxwidth=23.62
RoutingVias [All] p2: holewidth=16 width=34 viastyle="Through Hole" minholewidth=7.87 minwidth=24 maxholewidth=40 maxwidth=65
SilkToSilkClearance SilkToSilkClearance_Pb-FreeLogo [(HasFootprint('Pb-Free_Overlay_Medium') OR HasFootprint('Pb-Free_Overlay_Small')) vs (HasFootprint('Pb-Free_Overlay_Medium') OR HasFootprint('Pb-Free_Overlay_Small'))] p1: silktosilkclearance=0
SilkToSilkClearance [All] p2: silktosilkclearance=3.94
SilkToSolderMaskClearance SilkToComponentPadClearance [(IsPad or IsFill or IsRegion) and InAnycomponent] p1: minsilkscreentomaskgap=5 clearancetoexposedcopper=TRUE
SilkToSolderMaskClearance "Silk to Solder Mask Opening" [All] p2: minsilkscreentomaskgap=3.94 clearancetoexposedcopper=FALSE
SolderMaskExpansion [All] p1: expansion=1.97 istentingtop=FALSE
SupplyNets "Schematic Supply Nets_2" [InNet('PGND')] p1: voltage=0.000
SupplyNets "Schematic Supply Nets_1" [InNet('VCC_3v3')] p2: voltage=0.000
SupplyNets "Schematic Supply Nets" [InNet('QGND1')] p3: voltage=0.000
UnRoutedNet [All] p1: checkbadconnections=TRUE
Width [All] p1: maxlimit=100 minlimit=6 preferedwidth=10 checkconnectedcopper=TRUE
14 further rules are at their usual default settings.

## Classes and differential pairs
component class Header: J1
component class TIDA-050090-Page-1: C1 C2 C3 C4 C5 C6 C7 dVdT1 EN1 FLTBAR1 ILIM1 ILIM2 ILIM3 ILIM4 ILIM5 ILIM6 IMON1 IREF1 ITIMER1 J1 J2 NT1 NT2 NT3 NT4 OV1 PGOOD1 R1 R2 R3 R4 R5 R6 R7 R8 R9 R10 R11 R12 R13 R14 R15 R16 R17 R18 R19 R20 RZ1 RZ2 SWEN1 TEMP1 TP1 TP2 U1 U2
component class TIDA-050090-Page-2: C8 C9 C10 C11 C12 C13 C14 C15 C16 C17 C18 C19 C20 C21 C22 C23 C24 C25 C26 C27 C28 C29 C30 C31 D1 D2 D3 D4 D5 D6 D7 D8 D9 D10 J3 J4 J5 R21 R22 R23 R24 R25 R26 R27 R28 RCH1 U3 U4 U5 U6 U7 U8
component class "Mounting Holes": H1 H2 H3 H4
component class Logo: Logo2
component class Label: LBL1
component class FiducialMark: FID1 FID2 FID3
component class AssemblyNote: ZZ1 ZZ2 ZZ3 ZZ4
component class TIDA-050090-Hardware: !PCB FID1 FID2 FID3 H1 H2 H3 H4 H5 H6 H7 H8 L1 LBL1 Logo1 Logo2 Logo3 Logo4 LOGO5 LOGO6 ZZ1 ZZ2 ZZ3 ZZ4

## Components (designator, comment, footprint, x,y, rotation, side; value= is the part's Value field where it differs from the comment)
C1 "GRM155R61A683KA01D" 0402 2005.49,2564.86 r270 top value=0.068uF
C2 "GRM155R61A222KA01D" 0402 1872.04,3138.15 r90 top value=2200pF
C3 "C0402C100K4GACTU" 0402 1804.68,3138.15 r90 top value=10pF
C4 "GRJ188R71E105KE11D" 0603 2078.73,3422.53 r0 bottom value=1uF
C5 "CGA4J3X7S2A105K125AB" 0805_HV 553.53,715.51 r270 bottom value=1uF
C6 "GCM155R71H103KA55D" 0402 898.24,797.3 r270 bottom value=0.01uF
C7 "C0805C106J8RACAUTO" 0805_HV 1021.44,780.92 r270 bottom value=10uF
C8 "C1005X7S2A103K050BB" FP-C1005X7S2A103K050BB_0402-MFG 2065.25,3151.81 r270 top value=10nF
C9 "C1005X7S2A103K050BB" FP-C1005X7S2A103K050BB_0402-MFG 2062.29,2354.31 r270 top value=10nF
C10 "HMK107C7224MAHTE" 0603 2241.26,2504.17 r270 top value=0.22uF
C11 "HMK107C7224MAHTE" 0603 2245.2,1720.02 r270 top value=0.22uF
C12 "HMK107C7224MAHTE" 0603 2138.08,3125.9 r90 top value=0.22uF
C13 "HMK107C7224MAHTE" 0603 2135.13,2328.4 r90 top value=0.22uF
C14 "C1005X7S2A103K050BB" FP-C1005X7S2A103K050BB_0402-MFG 2067.86,1565.36 r270 top value=10nF
C15 "C1005X7S2A103K050BB" FP-C1005X7S2A103K050BB_0402-MFG 2065.25,3151.81 r270 bottom value=10nF
C16 "HMK107C7224MAHTE" 0603 2204.87,1022.99 r270 top value=0.22uF
C17 "HMK107C7224MAHTE" 0603 2241.26,2504.17 r270 bottom value=0.22uF
C18 "HMK107C7224MAHTE" 0603 2140.69,1539.45 r90 top value=0.22uF
C19 "HMK107C7224MAHTE" 0603 2025.2,2464.8 r180 bottom value=0.22uF
C20 "HMK107B7104KAHT" 0603 468.25,708.68 r270 bottom value=0.1uF
C21 "861221084017" WCAP-AIE8_D25H40 3515.19,1106.53 r90 top
C22 "HMK107B7104KAHT" 0603 2898.67,2131.55 r270 bottom value=0.1uF
C23 "C3225X7R2A105K200AA" 1210_220 2898.67,2133.41 r270 top value=1uF
C24 "CKG57NX7S2A226M500JH" CKG57N 2701.78,2123.57 r90 top value=22uF
C25 "CKG57NX7S2A226M500JH" CKG57N 2701.78,2123.57 r90 bottom value=22uF
C26 "C1005X7S2A103K050BB" FP-C1005X7S2A103K050BB_0402-MFG 2062.29,2354.31 r270 bottom value=10nF
C27 "C1005X7S2A103K050BB" FP-C1005X7S2A103K050BB_0402-MFG 2067.86,1565.36 r270 bottom value=10nF
C28 "HMK107C7224MAHTE" 0603 2245.2,1720.02 r270 bottom value=0.22uF
C29 "HMK107C7224MAHTE" 0603 2204.87,1022.99 r270 bottom value=0.22uF
C30 "HMK107C7224MAHTE" 0603 2042.66,1667.7 r180 bottom value=0.22uF
C31 "HMK107C7224MAHTE" 0603 2101.63,925.59 r180 bottom value=0.22uF
D1 "5.0SMDJ60A" SMC 1407.47,2947.08 r90 top value=60V
D2 "5.0SMDJ60A" SMC 1407.47,2113.9 r90 top value=60V
D3 "5.0SMDJ60A" SMC 1407.47,1303.38 r270 top value=60V
D4 "5.0SMDJ60A" SMC 1407.47,2947.08 r90 bottom value=60V
D5 "B380-13-F" SMC 2761.55,2947.08 r90 top value=80V
D6 "B380-13-F" SMC 2761.56,2947.08 r90 bottom value=80V
D7 "B380-13-F" SMC 2761.53,1306.56 r270 top value=80V
D8 "B380-13-F" SMC 2761.54,1306.56 r270 bottom value=80V
D9 "5.0SMDJ60A" SMC 1407.47,2113.9 r90 bottom value=60V
D10 "5.0SMDJ60A" SMC 1407.47,1303.38 r270 bottom value=60V
dVdT1 "5003" Keystone5003 1301.45,3787.53 r180 top
EN1 "5003" Keystone5003 1151.9,3788.05 r180 top
FID1 "Fiducial" Fiducial10-20 108.26,3678.58 r0 top
FID2 "Fiducial" Fiducial10-20 4045.27,3674.15 r0 top
FID3 "Fiducial" Fiducial10-20 4045.27,462.05 r0 top
FLTBAR1 "5003" Keystone5003 851.45,3788.53 r180 top
H1 "NY PMS 440 0025 PH" "NY PMS 440 0025 PH" 200,3940 r0 top
H2 "NY PMS 440 0025 PH" "NY PMS 440 0025 PH" 200,200 r0 top
H3 "NY PMS 440 0025 PH" "NY PMS 440 0025 PH" 3949.5,200 r0 top
H4 "NY PMS 440 0025 PH" "NY PMS 440 0025 PH" 3950,3940.5 r0 top
H5 "1902C" Keystone_1902C 200,3940 r180 bottom
H6 "1902C" Keystone_1902C 200,200 r180 bottom
H7 "1902C" Keystone_1902C 3950,200 r180 bottom
H8 "1902C" Keystone_1902C 3950,3940.5 r180 bottom
ILIM1 "5003" Keystone5003 2748.63,3786.27 r180 top
ILIM2 "5003" Keystone5003 2923.2,3786.38 r180 top
ILIM3 "5003" Keystone5003 3098.2,3785.94 r180 top
ILIM4 "5003" Keystone5003 3273.19,3786.77 r180 top
ILIM5 "5003" Keystone5003 3448.63,3786.27 r180 top
ILIM6 "5003" Keystone5003 3623.19,3786.77 r180 top
IMON1 "5003" Keystone5003 2573.68,3786.56 r180 top
IREF1 "5003" Keystone5003 2398.53,3786.57 r180 top
ITIMER1 "5003" Keystone5003 1600.98,3786.57 r180 top
J1 "PEC04SAAN" SULLINS_PEC04SAAN 1998.02,3790.57 r180 top
J2 "D3082-05" Harwin_D3082-05 3184.84,167.56 r0 top
J3 "B1-0-PCB-L" FP-B1-0-PCB-L_WIRE_LUG_150A_1-0AWG-MFG 588.99,2130.55 r180 top
J4 "B1-0-PCB-L" FP-B1-0-PCB-L_WIRE_LUG_150A_1-0AWG-MFG 3571.18,2130.55 r180 top
J5 "B1-0-PCB-L" FP-B1-0-PCB-L_WIRE_LUG_150A_1-0AWG-MFG 2069.68,346.14 r180 top
L1 "CAUTION HOT SURFACE" IEC_HotSurface_Small 229.99,708.66 r0 top
LBL1 "THT-14-423-10" Label_650x200 751.42,2774.24 r0 top
Logo1 "CE Mark" CE_Mark_5mm 972.96,3093.85 r0 top
Logo2 "Texas Instruments" TI_Stacked_Overlay_Small 639.75,1510.25 r0 top
Logo3 "FCC disclaimer" FCC_disclaimer 6318.9,1279.53 r0 top
Logo4 "WEEE logo" WEEE_Minimum 569.42,3143.06 r0 top
LOGO5 "DANGER HIGH VOLTAGE" IEC_HighVoltage_Small 205.99,2657.48 r0 top
LOGO6 "DANGER HIGH VOLTAGE" IEC_HighVoltage_Small 3937.01,2711.42 r0 top
NT1 "Net-Tie" NET-TIE_0805_HV_NOOVERLAY 1826.6,3581.41 r0 top net-tie
NT2 "Net-Tie" NET-TIE_0805_HV_NOOVERLAY 1826.6,3493.79 r0 top net-tie
NT3 "Net-Tie" NET-TIE_0805_HV_NOOVERLAY 1199.55,3618.69 r270 top net-tie
NT4 "Net-Tie" NET-TIE_0805_HV_NOOVERLAY 1001.57,3626.22 r270 top net-tie
OV1 "5003" Keystone5003 1001.9,3788.49 r180 top
PGOOD1 "5003" Keystone5003 701.45,3788.96 r180 top
R1 "RK73H1HTTC1004F" 0201 1734.28,2879.9 r180 top value=1.00Meg
R2 "RK73H1HTTC1004F" 0201 1732.86,3117.63 r90 top value=1.00Meg
R3 "RC0201FR-0740K2L" 0201 1953.35,2564.86 r90 top value=40.2k
R4 "RC0201DR-071K2L" 0201 1850,2564.86 r90 top value=1.20k
R5 "RC0201DR-071K2L" 0201 1916.59,1077.16 r90 top value=1.20k
R6 "RC0201DR-071K2L" 0201 1941.75,2273.8 r180 bottom value=1.20k
R7 "RC0201DR-071K2L" 0201 1911.02,1866.11 r90 top value=1.20k
R8 "RC0201DR-071K2L" 0201 1840.51,3118.46 r270 bottom value=1.20k
R9 "RC0201DR-071K2L" 0201 1947.3,1484.86 r180 bottom value=1.20k
R10 "RC0201FR-07549RL" 0201 1901.67,2564.86 r90 top value=549
R11 "RC0201FR-0718KL" 0201 1734.28,2907.71 r0 top value=18.0k
R12 "RC0201FR-7D47KL" 0201 1762.39,3117.59 r270 top value=47.0k
R13 "ERJ-2RKF3300X" 0402 2148.02,3656.34 r270 top value=330
R14 "ERJ-2RKF3300X" 0402 2048.02,3656.24 r270 top value=330
R15 "RC0201FR-7D150KL" 0201 2056.69,2564.86 r90 top value=150k
R16 "RC0201JR-0733KL" 0201 1907.91,3117.59 r90 top value=33k
R17 "CRCW040275K0FKED" 0402 1199.55,3495.46 r90 top value=75.0k
R18 "CRCW040275K0FKED" 0402 1001.57,3494.33 r90 top value=75.0k
R19 "CRCW040249K9FKED" 0402 948.26,797.3 r90 bottom value=49.9k
R20 "CRCW040290K9FKED" 0402 898.24,689.33 r90 bottom value=90.9k
R21 "CRCW0603150RFKEA" 0603 2106.58,3025.51 r180 top value=150
R22 "CRCW0603150RFKEA" 0603 2103.63,2228.01 r180 top value=150
R23 "RC0201JR-070RL" "FP-RC0201JR-070RL_0201 (0603 METRIC)-MFG" 1935.32,3162.56 r270 top
R24 "RC0201JR-070RL" "FP-RC0201JR-070RL_0201 (0603 METRIC)-MFG" 1961.97,3162.56 r270 top
R25 "CRCW0603150RFKEA" 0603 2109.2,1439.06 r180 top value=150
R26 "CRCW0603150RFKEA" 0603 2025.2,2564.86 r180 bottom value=150
R27 "CRCW0603150RFKEA" 0603 2042.66,1766.96 r180 bottom value=150
R28 "CRCW0603150RFKEA" 0603 2101.63,994.48 r180 bottom value=150
RCH1 "CRCW08050000Z0EA" 0805_HV 1505.9,974.05 r180 top value=0
RZ1 "CRCW04020000Z0ED" 0402 2086.61,3490.23 r180 bottom value=0
RZ2 "CRCW04020000Z0ED" 0402 1121.25,820.92 r180 bottom value=0
SWEN1 "5003" Keystone5003 551.45,3789.4 r180 top
TEMP1 "5003" Keystone5003 1451.62,3787.49 r180 top
TP1 "" Keystone5126 200.22,3055.35 r0 top
TP2 "" Keystone5126 842,203.66 r0 top
U1 "24FC08T-E/SN" FP-24FC08T-E_SN_SOIC8-MFG 2064.21,3497.53 r180 top
U2 "TPS7A4001DGNT" DGN0008B_N 740.54,710.86 r180 bottom
U3 "TPS16850VMAR" VMA0023A-MFG 1977.95,2842.5 r90 top
U4 "TPS16850VMAR" VMA0023A-MFG 1975,2045 r90 top
U5 "TPS16850VMAR" VMA0023A-MFG 1980.57,1256.06 r90 top
U6 "TPS16850VMAR" VMA0023A-MFG 1977.95,2842.5 r270 bottom
U7 "TPS16850VMAR" VMA0023A-MFG 1975.02,2045 r270 bottom
U8 "TPS16850VMAR" VMA0023A-MFG 1980.57,1256.06 r270 bottom
ZZ1 "This Assembly Note is for PCB labels only" AssemblyNoteLabel 9115.74,-422.99 r90 top
ZZ2 "These assemblies are ESD sensitive, ESD precautions shall be observed." AssemblyNote 9215.74,-422.99 r90 top
ZZ3 "These assemblies must be clean and free from flux and all contaminants. Use of no clean flux is not acceptable." AssemblyNote 9315.74,-422.99 r90 top
ZZ4 "These assemblies must comply with workmanship standards IPC-A-610 Class 2, unless otherwise specified." AssemblyNote 9415.74,-422.99 r90 top

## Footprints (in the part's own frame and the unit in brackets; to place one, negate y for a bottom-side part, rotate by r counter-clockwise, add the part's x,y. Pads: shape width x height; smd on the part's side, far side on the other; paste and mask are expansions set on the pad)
0201 [mm] "Data from Kemet datasheet CC101_COM dated 7/28/11"
  rect 0.46x0.42 smd mask+0.048: 1(-0.33,0) 2(0.33,0)
  silkscreen extent -0.75,-0.4 0.75,0.4, body extent -0.31,-0.16 0.31,0.16, height 0.26
0402 [mm] "0402 from SM-752 data"
  rect 0.8x0.6 smd: 1(-0.6,0) 2(0.6,0)
  silkscreen extent -1.22,-0.52 1.22,0.52, body extent -0.55,-0.3 0.55,0.3, height 0.6
0603 [mm] "0603 from SM-752 data"
  rect 1x0.95 smd: 1(-0.8,0) 2(0.8,0)
  silkscreen extent -1.52,-0.69 1.52,0.69, body extent -0.87,-0.47 0.87,0.47, height 1
0805_HV [mil] "0805 with 30mil clearance between pads"
  rect 50x63 smd: 1(-40,0) 2(40,0)
  silkscreen extent -74,-40 74,40, body extent -43,-29 43,29, height 57
1210_220 [mm] "1210"
  rect 1.3x2.7 smd: 1(-1.45,0) 2(1.45,0)
  silkscreen extent -2.32,-1.57 2.32,1.57, body extent -1.7,-1.35 1.7,1.35, height 2.2
AssemblyNote [mil] "Assembly Note"
AssemblyNoteLabel [mil] "Assembly Note for PCB Labels"
CE_Mark_5mm [mil] "Minimum text height for CE Mark"
  silkscreen extent -138,-98 138,98
CKG57N [mm] "Chip Capacitor, Body 6.0x5.0x5.0mm,"
  rect 2.6x5.75 smd mask+0.05: 1(-2.65,0) 2(2.65,0)
  silkscreen extent -0.81,-2.75 0.81,2.75, body extent -3.3,-2.75 3.3,2.75, height 5.5
DGN0008B_N [mm] "TSOP, 8-Leads, Body 3x3mm, Pitch 0.65mm, Thermal Pad 1.92x1.60mm, IPC Medium Density"
  rrect100% 1.35x0.45 smd: 1(-2.225,0.975) 2(-2.225,0.325) 3(-2.225,-0.325) 4(-2.225,-0.975) 5(2.225,-0.975) 6(2.225,-0.325) 7(2.225,0.325) 8(2.225,0.975)
  rrect5% 1.88x1.98 smd: 9(0,0)
  silkscreen extent -2.7,-1.55 0.95,1.55, body extent -2.46,-1.5 2.46,1.5, height 1.1
FCC_disclaimer [mil]
Fiducial10-20 [mm]
  round 1 smd mask+0.5: 1(0,0)
  Top Layer 1 keep-out circle w1.178: c0,0 r0.5
FP-24FC08T-E_SN_SOIC8-MFG [mm]
  rrect17% 1.55x0.6 smd paste+0 mask+0: 1(-2.7,1.905) 2(-2.7,0.635) 3(-2.7,-0.635) 4(-2.7,-1.905) 5(2.7,-1.905) 6(2.7,-0.635) 7(2.7,0.635) 8(2.7,1.905)
  silkscreen extent -4.23,-2.5 1.55,2.5, body extent -3.57,-2.75 3.57,2.75, height 0.25
FP-B1-0-PCB-L_WIRE_LUG_150A_1-0AWG-MFG [mil]
  rrect100% 96.61x430 hole 72.99 slot 400 at 90 deg paste-99999 mask+0: 1(-380,0) 1(380,0)
  silkscreen extent -320,-289 320,289, body extent -432,-292 432,292, height 10
FP-C1005X7S2A103K050BB_0402-MFG [mm]
  rrect25% 0.4x0.5 smd paste+0 mask+0: 1(-0.4,0) 2(0.4,0)
  silkscreen extent -0.53,-0.65 0.53,0.65, body extent -0.7,-0.38 0.7,0.38, height 0.25
"FP-RC0201JR-070RL_0201 (0603 METRIC)-MFG" [mm]
  rrect29% 0.35x0.4 smd paste+0 mask+0: 1(-0.325,0) 2(0.325,0)
  silkscreen extent -0.08,-0.16 0.07,0.16, body extent -0.6,-0.3 0.6,0.3, height 0.25
Harwin_D3082-05 [mm] "Shorting Plug, 10.16mm spacing, TH"
  round 1.8 hole 1.3: 1(-5.08,0) 2(5.08,0)
  silkscreen extent -3.9,-0.53 3.9,0.53, body extent -5.6,-0.52 5.61,0.52, height 6.63
IEC_HighVoltage_Small [mil]
  silkscreen extent -107,-88 107,97
IEC_HotSurface_Small [mil]
  silkscreen extent -107,-93 107,92
Keystone5003 [mil] "For Keystone 500x miniature loop terminals"
  round 80 hole 40: 1(0,0)
  silkscreen extent -52,-52 52,52, body extent -49,-49 49,49, height 182
Keystone5126 [mil] "Keystone Multipurpose loops"
  round 87 hole 63: 1(0,0)
  silkscreen extent -70,-70 70,70, body extent -63,-63 63,62, height 319
Keystone_1902C [mil] "Hex Standoff, 4-40 threaded, nylon"
  round 1 on Mech3: 0(0,0)
  body extent -145,-126 146,126, height 501
Label_650x200 [mil] "Thermal Transfer Label"
  round 1 on Mech13: 0(0,0)
  silkscreen extent -325,-100 325,100, body extent -325,-100 325,100, height 1
NET-TIE_0805_HV_NOOVERLAY [mil] "0805_HV pads tied by 10mil copper trace which can be cut.  An 0805 part can be placed on pads."
  rect 50x63 smd paste-25 mask-1000: 1(-40,0) 2(40,0)
  Top Layer 1 lines w10: -16,0 16,0
  Top Layer 1 keep-out lines w1: -22,-30.91 -22,30.91 ; -14.96,-30.91 14.96,-30.91 ; -14.96,30.91 14.96,30.91 ; 22,-30.91 22,30.91
"NY PMS 440 0025 PH" [mm] "4-40 nylon screw and mounting hole"
  round 8 hole 3.2 unplated: 1(0,0)
  body extent -3.3,-3.3 3.3,3.3, height 2.69
SMC [mil] "Molded Diode, 2-Leads, Body 6.9x5.8mm, IPC Medium Density, based on OnSemi component dimensions and land patterns"
  rect 110x150 smd mask+1.97: 1(-140.49,0) 2(140.49,0)
  silkscreen extent -221,-126 189,165, body extent -156,-116 156,116, height 91
SULLINS_PEC04SAAN [mm] "SULLINS"
  rect 1.65x1.65 hole 1: 1(-3.81,0)
  round 1.65 hole 1: 2(-1.27,0) 3(1.27,0) 4(3.81,0)
  silkscreen extent -5.59,-1.4 5.21,1.52, body extent -5.21,-1.33 5.21,1.33, height 8.38
TI_Stacked_Overlay_Small [mil]
  silkscreen extent -418,-98 418,98
VMA0023A-MFG [mm]
  rrect40% 0.65x0.25 smd paste+0 mask+0: 1(-2.875,0.5) 2(-2.875,0) 3(-2.875,-0.5) 4(-2.875,-1) 11(2.875,-0.925) 12(2.875,-0.425) 13(2.875,0.075) 14(2.875,0.575) 15(2.875,1.075) 16(2.875,1.575)
  rrect40% 0.7x0.25 smd paste+0 mask+0: 5(-2.85,-1.5)
  round 0.235 smd paste+0 mask+0: 6(-2.675,-2.175)
  round 0.765 smd paste+0 mask+0: 7(-0.925,-2.325)
  rrect40% 0.25x0.75 smd paste+0 mask+0: 8(0.225,-2.325) 9(1.275,-2.325)
  round 0.855 smd paste+0 mask+0: 10(2.425,-2.275)
  round 0.27 smd paste+0 mask+0: 17(2.375,2.05)
  rrect40% 0.25x0.6 smd paste+0 mask+0: 18(1.85,2.4) 19(1.35,2.4) 20(0.85,2.4) 21(0.35,2.4)
  round 0.788 smd paste+0 mask+0: 22(-2.1,2.312)
  rrect40% 1.3x0.25 smd paste+0 mask+0: 23(-2.55,1.55)
  rrect4% 3.4x2.35 smd paste+0 mask+0: 24(0,0.075)
  Top Layer 1 region: -1.67,-2.75 -1.707,-2.735 -1.735,-2.707 -1.75,-2.67 -1.75,-2.65 -1.75,-2.075 -1.75,-2.04 -1.723,-1.976 -1.674,-1.927 -1.61,-1.9 -1.575,-1.9 -0.275,-1.9 -0.24,-1.9 -0.176,-1.927 -0.127,-1.976 -0.1,-2.04 -0.1,-2.075 -0.1,-2.67 -0.115,-2.707 -0.143,-2.735 -0.18,-2.75 -0.2,-2.75
  Top Layer 1 region: -1.03,2.75 -0.993,2.735 -0.965,2.707 -0.95,2.67 -0.95,2.65 -0.95,1.975 -0.95,1.955 -0.965,1.918 -0.993,1.89 -1.03,1.875 -1.05,1.875 -3.15,1.875 -3.17,1.875 -3.207,1.89 -3.235,1.918 -3.25,1.955 -3.25,1.975 -3.25,2.65 -3.25,2.67 -3.235,2.707 -3.207,2.735 -3.17,2.75 -3.15,2.75
  Top Layer 1 region: 3.17,-1.8 3.207,-1.815 3.235,-1.843 3.25,-1.88 3.25,-1.9 3.25,-2.65 3.25,-2.67 3.235,-2.707 3.207,-2.735 3.17,-2.75 1.68,-2.75 1.643,-2.735 1.615,-2.707 1.6,-2.67 1.6,-2.65 1.6,-1.975 1.6,-1.94 1.627,-1.876 1.676,-1.827 1.74,-1.8 1.775,-1.8
  Top Layer 1 region: -3.15,-2.125 -3.16,-2.125 -3.178,-2.117 -3.192,-2.103 -3.2,-2.085 -3.2,-1.915 -3.192,-1.897 -3.178,-1.883 -3.16,-1.875 -2.55,-1.875 -2.54,-1.875 -2.522,-1.883 -2.508,-1.897 -2.5,-1.915 -2.5,-1.925 -2.5,-2.65 -2.5,-2.66 -2.508,-2.678 -2.522,-2.692 -2.54,-2.7 -2.55,-2.7 -2.76,-2.7 -2.778,-2.692 -2.792,-2.678 -2.8,-2.66 -2.8,-2.65 -2.8,-2.225 -2.802,-2.205 -2.817,-2.169 -2.844,-2.142 -2.88,-2.127 -2.9,-2.125
  Top Layer 1 region: 3.15,2.15 3.16,2.15 3.178,2.142 3.192,2.128 3.2,2.11 3.2,2.1 3.2,1.95 3.2,1.94 3.192,1.922 3.178,1.908 3.16,1.9 3.15,1.9 2.35,1.9 2.325,1.9 2.279,1.919 2.244,1.954 2.225,2 2.225,2.025 2.225,2.65 2.225,2.66 2.233,2.678 2.247,2.692 2.265,2.7 2.275,2.7 2.425,2.7 2.435,2.7 2.453,2.692 2.467,2.678 2.475,2.66 2.475,2.65 2.475,2.25 2.477,2.23 2.492,2.194 2.519,2.167 2.555,2.152 2.575,2.15
  silkscreen extent -3.87,-2.93 3.42,2.93, body extent -3,-2.5 3,2.5, height 1.5
WCAP-AIE8_D25H40 [mm] "Aluminium Electrolytic Snap-In Capacitors, 25x40mm"
  rrect50% 3x3 hole 2: 1(5,0)
  round 3 hole 2: 2(-5,0)
  silkscreen extent -13,-13 13,13, body extent -12.46,-12.5 12.5,12.5, height 41.09
WEEE_Minimum [mil] "WEEElie bin"
  silkscreen extent -95,-172 99,104

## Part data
C1: library part CMP-0006585-2, "CAP, CERM, 0.068 uF, 10 V, +/- 10%, X5R, 0402", Cap_Case=0402, Manufacturer=MuRata, Supplier Part Number 1=490-1317-1-ND, TempCo=X5R, Tolerance_%=10%, Value1=Unknown, Value2=10V, ValueDisplayed=0.068uF
C2: library part CMP-0006569-2, "CAP, CERM, 2200 pF, 10 V, +/- 10%, X5R, 0402", Cap_Case=0402, Manufacturer=MuRata, Supplier Part Number 1=GRM155R61A222KA01D-ND, TempCo=X5R, Tolerance_%=10%, Value1=Unknown, Value2=10V, ValueDisplayed=2200pF
C3: library part CMP-0079539-1, "CAP, CERM, 10 pF, 16 V,+/- 10%, C0G, 0402", Cap_Case=0402, Manufacturer=Kemet, Supplier Part Number 1=399-11110-1-ND, TempCo=C0G, Tolerance_%=10%, Value2=16V, ValueDisplayed=10pF
C4: library part CMP-0079720-1, "CAP, CERM, 1 µF, 25 V,+/- 10%, X7R, 0603", Cap_Case=0603, Manufacturer=MuRata, Supplier Part Number 1=490-10888-1-ND, TempCo=X7R, Tolerance_%=10%, Value2=25V, ValueDisplayed=1µF
C5: library part CMP-0007980-1, "CAP, CERM, 1 uF, 100 V, +/- 10%, X7S, AEC-Q200 Grade 1, 0805", Cap_Case=0805, Manufacturer=TDK, Supplier Part Number 1=445-6974-1-ND, TempCo=X7S, Tolerance_%=10%, Value1="0.008255 ohm", Value2=100V, ValueDisplayed=1uF
C6: library part CMP-0006355-1, "CAP, CERM, 0.01 uF, 50 V, +/- 10%, C0G/NP0, 0402", Cap_Case=0402, Manufacturer=MuRata, Supplier Part Number 1=490-4762-1-ND, TempCo=C0G/NP0, Tolerance_%=10%, Value1=Unknown, Value2=50V, ValueDisplayed=0.01uF
C7: library part CMP-0081061-1, "CAP, CERM, 10 µF, 10 V,+/- 5%, X7R, AEC-Q200 Grade 1, 0805", Cap_Case=0805, Manufacturer=Kemet, Supplier Part Number 1=399-15693-1-ND, TempCo=X7R, Tolerance_%=5%, Value2=10V, ValueDisplayed=10µF
C8 C9 C14 C15 C26 C27: library part CMP-0121600-1, "Multilayer Ceramic Capacitors 10nF ±10% 100V X7S SMD 0402", Manufacturer=TDK, Operating Temperature Range="-55°C to +125°C", TempCo=0.22, Temperature Characteristic=X7S, Tolerance_%=0.1%, ValueDisplayed=10nF
C10 C11 C16 C17 C28 C29: library part CMP-0077895-2, "CAP, CERM, 0.22 µF, 100 V,+/- 20%, X7S, AEC-Q200 Grade 1, 0603", Cap_Case=0603, Manufacturer="Taiyo Yuden", Supplier Part Number 1=587-5013-1-ND, TempCo=X7S, Tolerance_%=20%, Value2=100V, ValueDisplayed=0.22µF
C12 C13 C18 C19 C30 C31: library part CMP-0077895-3, "CAP, CERM, 0.22 µF, 100 V,+/- 20%, X7S, AEC-Q200 Grade 1, 0603", Cap_Case=0603, Manufacturer="Taiyo Yuden", Supplier Part Number 1=587-5013-1-ND, TempCo=X7S, Tolerance_%=20%, Value2=100V, ValueDisplayed=0.22µF
C20 C22: library part CMP-0081011-1, "CAP, CERM, 0.1 µF, 100 V,+/- 10%, X7R, AEC-Q200 Grade 1, 0603", Cap_Case=0603, Manufacturer="Taiyo Yuden", Supplier Part Number 1=587-6009-1-ND, TempCo=X7R, Tolerance_%=10%, Value2=100V, ValueDisplayed=0.1µF
C21: library part CMP-0117576-1, "WCAP-AIE8 Aluminum Electrolytic Capacitor, Snap-In, D25 x H40mm, 1000µF, 200V", Capacitance Tolerance=+/-20%, Leakage Current=1341.64uA, Manufacturer="Wurth Elektronik", Operating Temperature Max=85°C, Operating Temperature Min=-25°C, Rated Voltage (DC)=200V, Ripple Current=3280mA
C23: library part CMP-0009125-1, "CAP, CERM, 1 uF, 100 V, +/- 10%, X7R, 1210", Cap_Case=1210_220, Manufacturer=TDK, Supplier Part Number 1=445-2294-1-ND, TempCo=X7R, Tolerance_%=10%, Value1="0.004956 ohm", Value2=100V, ValueDisplayed=1uF
C24 C25: library part CMP-0860250-1, "CAP, CERM, 22 µF,  VAC/100 VDC,+/- 20%, X7S, 6x5x5mm", Manufacturer=TDK, Supplier Part Number 1=445-5217-1-ND, TempCo=X7S, Tolerance_%=20%, Value2=100V, ValueDisplayed=22µF
D1 D2 D3 D4 D9 D10: library part CMP-0005717-3, "Diode, TVS, Uni, 60 V, 96.8 Vc, SMC", Manufacturer=Littelfuse, Value1=5000W
D5 D6 D7 D8: library part CMP-0028422-1, "Diode, Schottky, 80 V, 3 A, SMC", Manufacturer="Diodes Inc.", Supplier Part Number 1=B380-FDICT-ND, Value1=3A, Value2=0.79V
dVdT1 EN1 FLTBAR1 ILIM1 ILIM2 ILIM3 ILIM4 ILIM5 ILIM6 IMON1 IREF1 ITIMER1 OV1 PGOOD1 SWEN1 TEMP1: library part CMP-0055140-1, "Test Point, Miniature, Orange, TH", Color=Orange, Manufacturer=Keystone, Supplier Part Number 1=36-5003-ND
FID1 FID2 FID3: library part CMP-0077181-1, "Fiducial mark.  There is nothing to buy or mount.", Manufacturer=N/A
H1 H2 H3 H4: library part CMP-0003617-1, "Machine Screw, Round, #4-40 x 1/4, Nylon, Philips panhead", Manufacturer="B&F Fastener Supply", Supplier Part Number 1=H542-ND
H5 H6 H7 H8: library part CMP-0003610-1, "Standoff, Hex, 0.5\"L #4-40 Nylon", Manufacturer=Keystone, Supplier Part Number 1=36-1902C-ND
J1: library part CMP-0054562-1, "Header, 100mil, 4x1, Tin, TH", Color=Black, Current_A=3A, Manufacturer="Sullins Connector Solutions", Supplier Part Number 1=S1012E-04-ND, Voltage_V=1.8kV
J2: library part CMP-0075110-1, "1mm Uninsulated Shorting Plug, 10.16mm spacing, TH", Manufacturer=Harwin, Supplier Part Number 1=952-1873-ND
J3 J4 J5: library part CMP-0093713-1, "1/0 AWG High AMP PCB Wire Lugs 1/0-8 AWG", Current_A=150A, Manufacturer="INTERNATIONAL HYDRAULICS", Operating Temperature Range=to
L1: library part CMP-0074837-1, "IEC 61010-1 Hot Surface Warning"
LBL1: library part CMP-0003625-1, "Thermal Transfer Printable Labels, 0.650\" W x 0.200\" H - 10,000 per roll", Manufacturer=Brady, Supplier Part Number 1=97C5133
Logo1: library part CMP-0074844-1
Logo2: library part CMP-0074838-1, "Texas Instrument Corporate Signature"
Logo3: library part CMP-0074847-1, "FCC_disclaimer"
Logo4: library part CMP-0074769-1
LOGO5 LOGO6: library part CMP-0074835-1, "IEC 61010-1 High Voltage Warning"
NT1 NT2 NT3 NT4: library part CMP-0078142-6, "Single point connection between nets.", Manufacturer=N/A
R1 R2: library part CMP-0028122-1, "RES, 1.00 M, 1%, 0.05 W, AEC-Q200 Grade 0, 0201", Manufacturer="KOA Speer", Power_W=50mW, Supplier Part Number 1=660-RK73H1HTTC1004F, TempCo="200 ppm/C", Tolerance_%=1%, Value2=0.05W, Value_Code=1M00, ValueDisplayed=1.00M
R3: library part CMP-0027688-1, "RES, 40.2 k, 1%, 0.05 W, 0201", Manufacturer="Yageo America", Power_W=50mW, Supplier Part Number 1=YAG2286CT-ND, TempCo="200 ppm/C", Tolerance_%=1%, Value2=0.05W, Value_Code=40k2, ValueDisplayed=40.2k
R4 R5 R6 R7 R8 R9: library part CMP-0028147-1, "RES, 1.20 k, 0.5%, 0.05 W, 0201", Manufacturer="Yageo America", Power_W=50mW, Supplier Part Number 1=RC0201DR-071K2L-ND, TempCo="200 ppm/C", Tolerance_%=0.5%, Value2=0.05W, Value_Code=1k20, ValueDisplayed=1.20k
R10: library part CMP-0027769-1, "RES, 549, 1%, 0.05 W, 0201", Manufacturer="Yageo America", Power_W=50mW, Supplier Part Number 1=YAG2725CT-ND, TempCo="200 ppm/C", Tolerance_%=1%, Value2=0.05W, Value_Code=549R, ValueDisplayed=549
R11: library part CMP-0027410-1, "RES, 18.0 k, 1%, 0.05 W, 0201", Manufacturer="Yageo America", Power_W=50mW, Supplier Part Number 1=311-18.0KMCT-ND, TempCo="200 ppm/C", Tolerance_%=1%, Value2=0.05W, Value_Code=18k0, ValueDisplayed=18.0k
R12: library part CMP-0028024-1, "RES, 47.0 k, 1%, 0.05 W, 0201", Manufacturer="Yageo America", Power_W=50mW, Supplier Part Number 1=603-RC0201FR-7D47KL, TempCo="200 ppm/C", Tolerance_%=1%, Value2=0.05W, Value_Code=47k0, ValueDisplayed=47.0k
R13 R14: library part CMP-0026694-1, "RES, 330, 1%, 0.1 W, AEC-Q200 Grade 0, 0402", Manufacturer=Panasonic, Power_W=100mW, Supplier Part Number 1=P330LCT-ND, TempCo="100 ppm/C", Tolerance_%=1%, Value2=0.1W, Value_Code=330R, ValueDisplayed=330
R15: library part CMP-0027959-1, "RES, 150 k, 1%, 0.05 W, 0201", Manufacturer="Yageo America", Power_W=50mW, Supplier Part Number 1=603-RC0201FR-7D150KL, TempCo="200 ppm/C", Tolerance_%=1%, Value2=0.05W, Value_Code=150k
R16: library part CMP-0027101-1, "RES, 33 k, 5%, 0.05 W, 0201", Manufacturer="Yageo America", Power_W=50mW, Supplier Part Number 1=311-33KNCT-ND, TempCo="200 ppm/C", Tolerance_%=5%, Value2=0.05W, Value_Code=33k0, ValueDisplayed=33k
R17 R18: library part CMP-0026543-1, "RES, 75.0 k, 1%, 0.063 W, 0402", Manufacturer=Vishay-Dale, Power_W=63mW, Supplier Part Number 1=541-75.0KLCT-ND, TempCo="100 ppm/C", Tolerance_%=1%, Value2=0.063W, Value_Code=75k0, ValueDisplayed=75.0k
R19: library part CMP-0026403-1, "RES, 49.9 k, 1%, 0.063 W, 0402", Manufacturer=Vishay-Dale, Power_W=63mW, Supplier Part Number 1=541-49.9KLCT-ND, TempCo="100 ppm/C", Tolerance_%=1%, Value2=0.063W, Value_Code=49k9, ValueDisplayed=49.9k
R20: library part CMP-0026605-1, "RES, 90.9 k, 1%, 0.063 W, 0402", Manufacturer=Vishay-Dale, Power_W=63mW, Supplier Part Number 1=541-90.9KLCT-ND, TempCo="100 ppm/C", Tolerance_%=1%, Value2=0.063W, Value_Code=90k9, ValueDisplayed=90.9k
R21 R22 R25 R26 R27 R28: library part CMP-0022061-4, "RES, 150, 1%, 0.1 W, 0603", Manufacturer=Vishay-Dale, Power_W=100mW, Supplier Part Number 1=541-150HCT-ND, TempCo="100 ppm/C", Tolerance_%=1%, Value2=0.1W, Value_Code=150R, ValueDisplayed=150
R23 R24: library part CMP-0086442-1, "RES SMD 0 OHM JUMPER 1/20W 0201", Manufacturer=Yageo, Power_W=50mW, TempCo=200ppm/°C, Tolerance_%=5%
RCH1: library part CMP-0020442-3, "RES, 0, 5%, 0.125 W, AEC-Q200 Grade 0, 0805", Manufacturer=Vishay-Dale, Power_W=125mW, Supplier Part Number 1=541-0.0ACT-ND, TempCo="200 ppm/C", Tolerance_%=5%, Value2=0.125W, Value_Code=0000, ValueDisplayed=0
RZ1 RZ2: library part CMP-0026822-3, "RES, 0, 5%, 0.063 W, AEC-Q200 Grade 0, 0402", Manufacturer=Vishay-Dale, Power_W=63mW, Supplier Part Number 1=541-0.0JCT-ND, TempCo="200 ppm/C", Tolerance_%=5%, Value2=0.063W, Value_Code=0000, ValueDisplayed=0
TP1 TP2: library part CMP-0055158-1, "Test Point, Multipurpose, Green, TH", Color=Green, Manufacturer=Keystone, PartNumber=5126, Supplier Part Number 1=36-5126-ND
U1: library part CMP-0094711-2, "EEPROM Memory IC 8Kb (1K x 8) I²C 1 MHz 450 µs 8-SOIC", Digikey Part Number=150-24FC08T-E/SNCT-ND, Frequency_Fixed=400kHz, Manufacturer=Microchip, Max Supply Voltage=5.5V, Min Supply Voltage=1.7V, Mouser Part Number=579-24FC08T-E/SN, Nominal Supply Current=1-3mA, Operating Temperature Range="-40°C to +125°C"
U2: library part CMP-0035947-1, "Single Output LDO, 50 mA, Adjustable 1.175 to 90 V Output, 7 to 100 V Input, 8-pin MSOP (DGN), -40 to 125 degC, Green (RoHS & no Sb/Br)", Manufacturer="Texas Instruments"
U3 U4 U5 U6 U7 U8: library part CMP-0120541-1, "9 - 80 V , 4.3 mΩ, 20 A Stackable eFuse with Accurate & Fast Current Monitor", Manufacturer="Texas Instruments", Max Supply Voltage=80V, Min Supply Voltage=9V, Operating Temperature Range="-40°C to +125°C"
ZZ1: library part CMP-0003616-3
ZZ2: library part CMP-0077236-1
ZZ3: library part CMP-0077237-1
ZZ4: library part CMP-0077238-1

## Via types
v1: diameter 24, hole 12, Top Layer 1 to Bottom Layer 1, tented both sides, 1740 vias
v2: diameter 20, hole 10, Top Layer 1 to Bottom Layer 1, tented both sides, 444 vias
v3: diameter 16, hole 8, Top Layer 1 to Bottom Layer 1, tented both sides, 67 vias
v4: diameter 19.68, hole 7.87, Top Layer 1 to Bottom Layer 1, tented both sides, 41 vias

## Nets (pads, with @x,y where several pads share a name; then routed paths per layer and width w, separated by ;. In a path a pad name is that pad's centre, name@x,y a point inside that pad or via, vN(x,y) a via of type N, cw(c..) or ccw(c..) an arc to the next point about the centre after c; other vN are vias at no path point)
ADDR0: NT3.2 R17.2 | length 59.6
  Top Layer 1 w10: R17.2@1199.55,3519.09 NT3.2@1199.55,3578.69
ADDR1: NT4.2 R18.2 | length 68.3
  Top Layer 1 w10: R18.2@1001.57,3517.95 NT4.2@1001.57,3586.22
dVdT: C1.1 dVdT1.1 U3.4 U4.4 U5.4 U6.4 U7.4 U8.4 | length 4546.8
  Top Layer 1 w10: C1.1@2005.49,2588.48 v3(2005.49,2657.09) 2005.49,2678.99 2017.32,2690.82 U3.4@2017.32,2729.31 ; v3(2014.37,1877.37) U4.4@2014.37,1931.81 ; U5.4@2019.94,1142.87 2019.94,1121.24 2042.5,1098.68 v3(2042.5,1084.24)
  SIGNAL1 w10: dVdT1.1@1301.45,3787.53 1407.25,3893.32 2185.48,3893.32 2238.47,3840.33 2238.47,3504.68 2113.84,3380.05 2113.84,3068.56 2093.53,3048.25 v3(2019.21,3048.25) 2019.21,2985.91 2059.77,2945.35 2059.77,2726.82 2058.01,2725.06 2005.49,2672.54 2005.49,2662.02 v3(2005.49,2657.09) 2005.49,2548.57 2037.4,2516.66 2037.4,2451.18 2018.22,2432 2018.22,2273.34 2037.4,2254.16 2037.4,2235.46 v3(2016.28,2214.33) 2016.28,2179.85 2057.09,2139.04 2057.09,1920.08 v3(2014.37,1877.37) 2049.61,1842.13 2049.61,1631.71 2027.56,1609.66 2027.56,1480.75 2043.41,1464.89 2043.41,1446.97 v3(2021.83,1425.39) 2021.83,1388.56 2065.03,1345.36 2065.03,1106.77 v3(2042.5,1084.24)
  Bottom Layer 1 w10: U7.4@2014.39,2158.19 2014.39,2192.95 2016.28,2194.84 v3(2016.28,2214.33) ; U6.4@2017.32,2955.69 2017.32,3026.87 2019.21,3028.76 v3(2019.21,3048.25) ; U8.4@2019.94,1369.24 2019.94,1404.01 2021.83,1405.89 v3(2021.83,1425.39)
EECLK: NT2.2 U1.6 | length 103.2
  Top Layer 1 w20: NT2.2@1866.6,3493.79 1895.27,3493.79 1924.01,3522.53 U1.6@1957.91,3522.53
EEDATA: NT1.2 U1.5 | length 95.3
  Top Layer 1 w20: NT1.2@1866.6,3581.41 1866.93,3581.73 1899.6,3581.73 1908.8,3572.53 U1.5@1957.91,3572.53
Efuse1_ILIM: ILIM1.1 R4.2 U3.1 | length 1982.6
  Top Layer 1 w10: R4.2@1850,2577.85 v3(1850,2598.29) 1850,2603.24 1958.27,2711.51 U3.1@1958.27,2729.31
  SIGNAL2 w10: v3(1850,2598.29) 1861.56,2586.73 2010.27,2586.73 2076.76,2653.23 2076.76,3007.63 2114.5,3045.37 2114.5,3349.84 2449.93,3685.27 2647.63,3685.27 ILIM1.1@2748.63,3786.27
Efuse2_ILIM: ILIM2.1 R5.2 U5.1 | length 3575.2
  Top Layer 1 w10: R5.2@1916.59,1090.16 v3(1940.5,1090.16) 1960.88,1110.54 U5.1@1960.88,1142.87
  SIGNAL2 w10: v3(1940.5,1090.16) 1940.5,1047.09 1973.11,1014.48 2001.44,1014.48 2065.89,1078.94 2065.89,1103.62 2082.08,1119.81 2082.08,1378.34 2142,1438.26 2142,1522.45 2171.68,1552.13 2447.98,1552.13 2493.44,1597.6 2493.44,3454.01 2604.56,3565.13 2701.95,3565.13 ILIM2.1@2923.2,3786.38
